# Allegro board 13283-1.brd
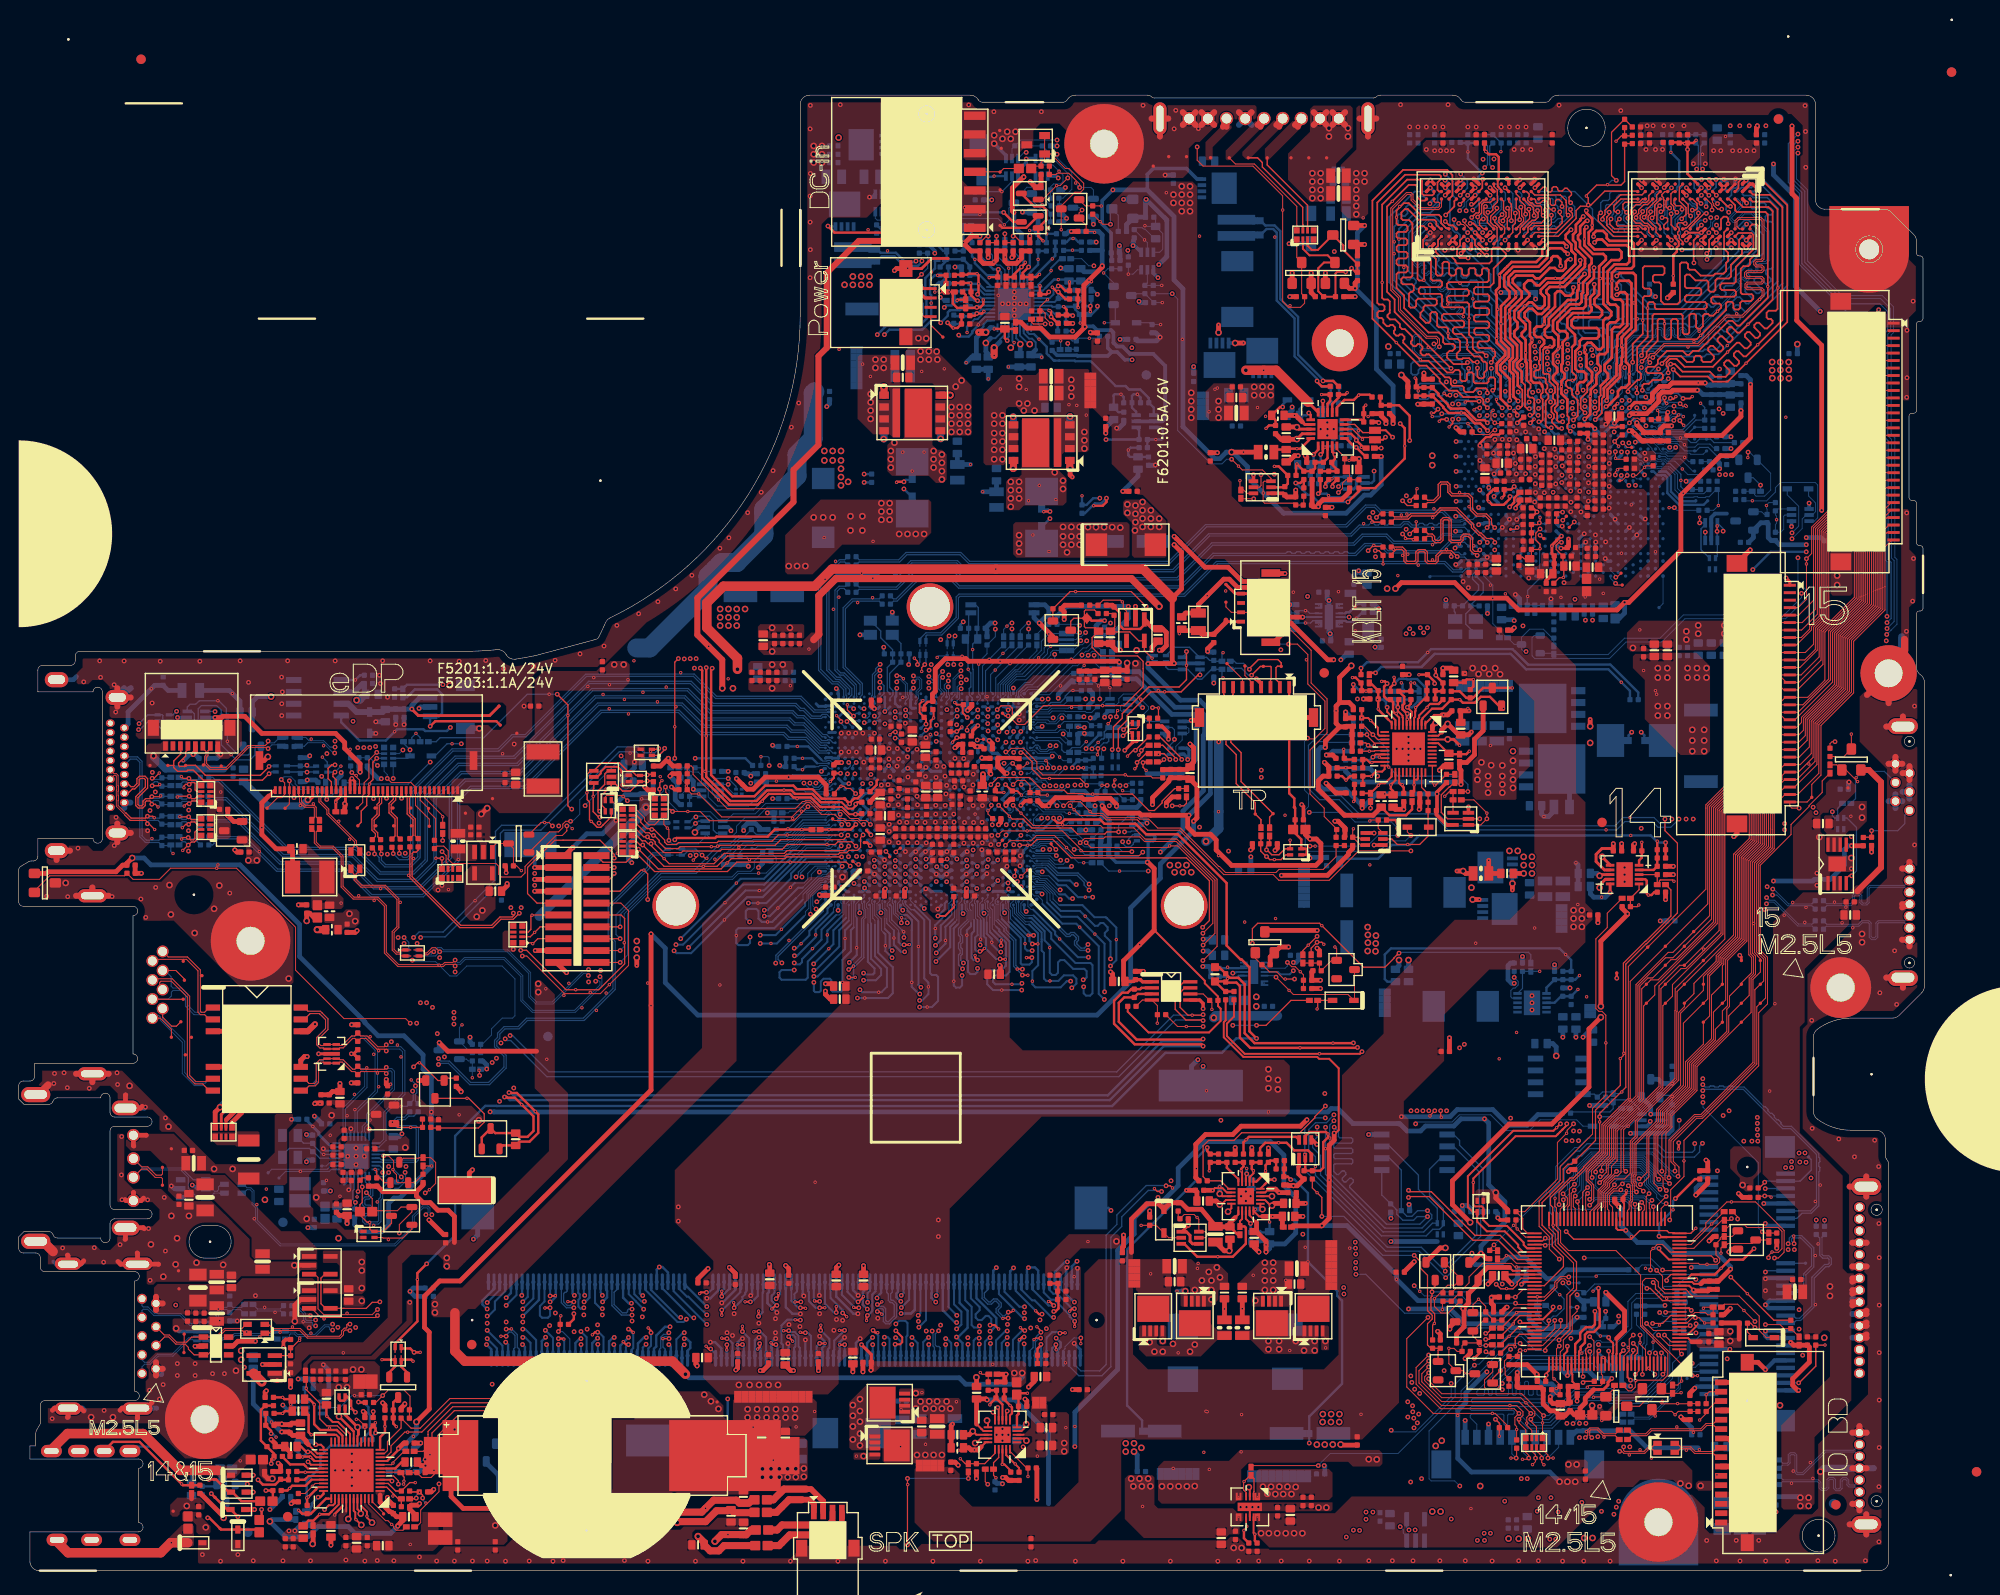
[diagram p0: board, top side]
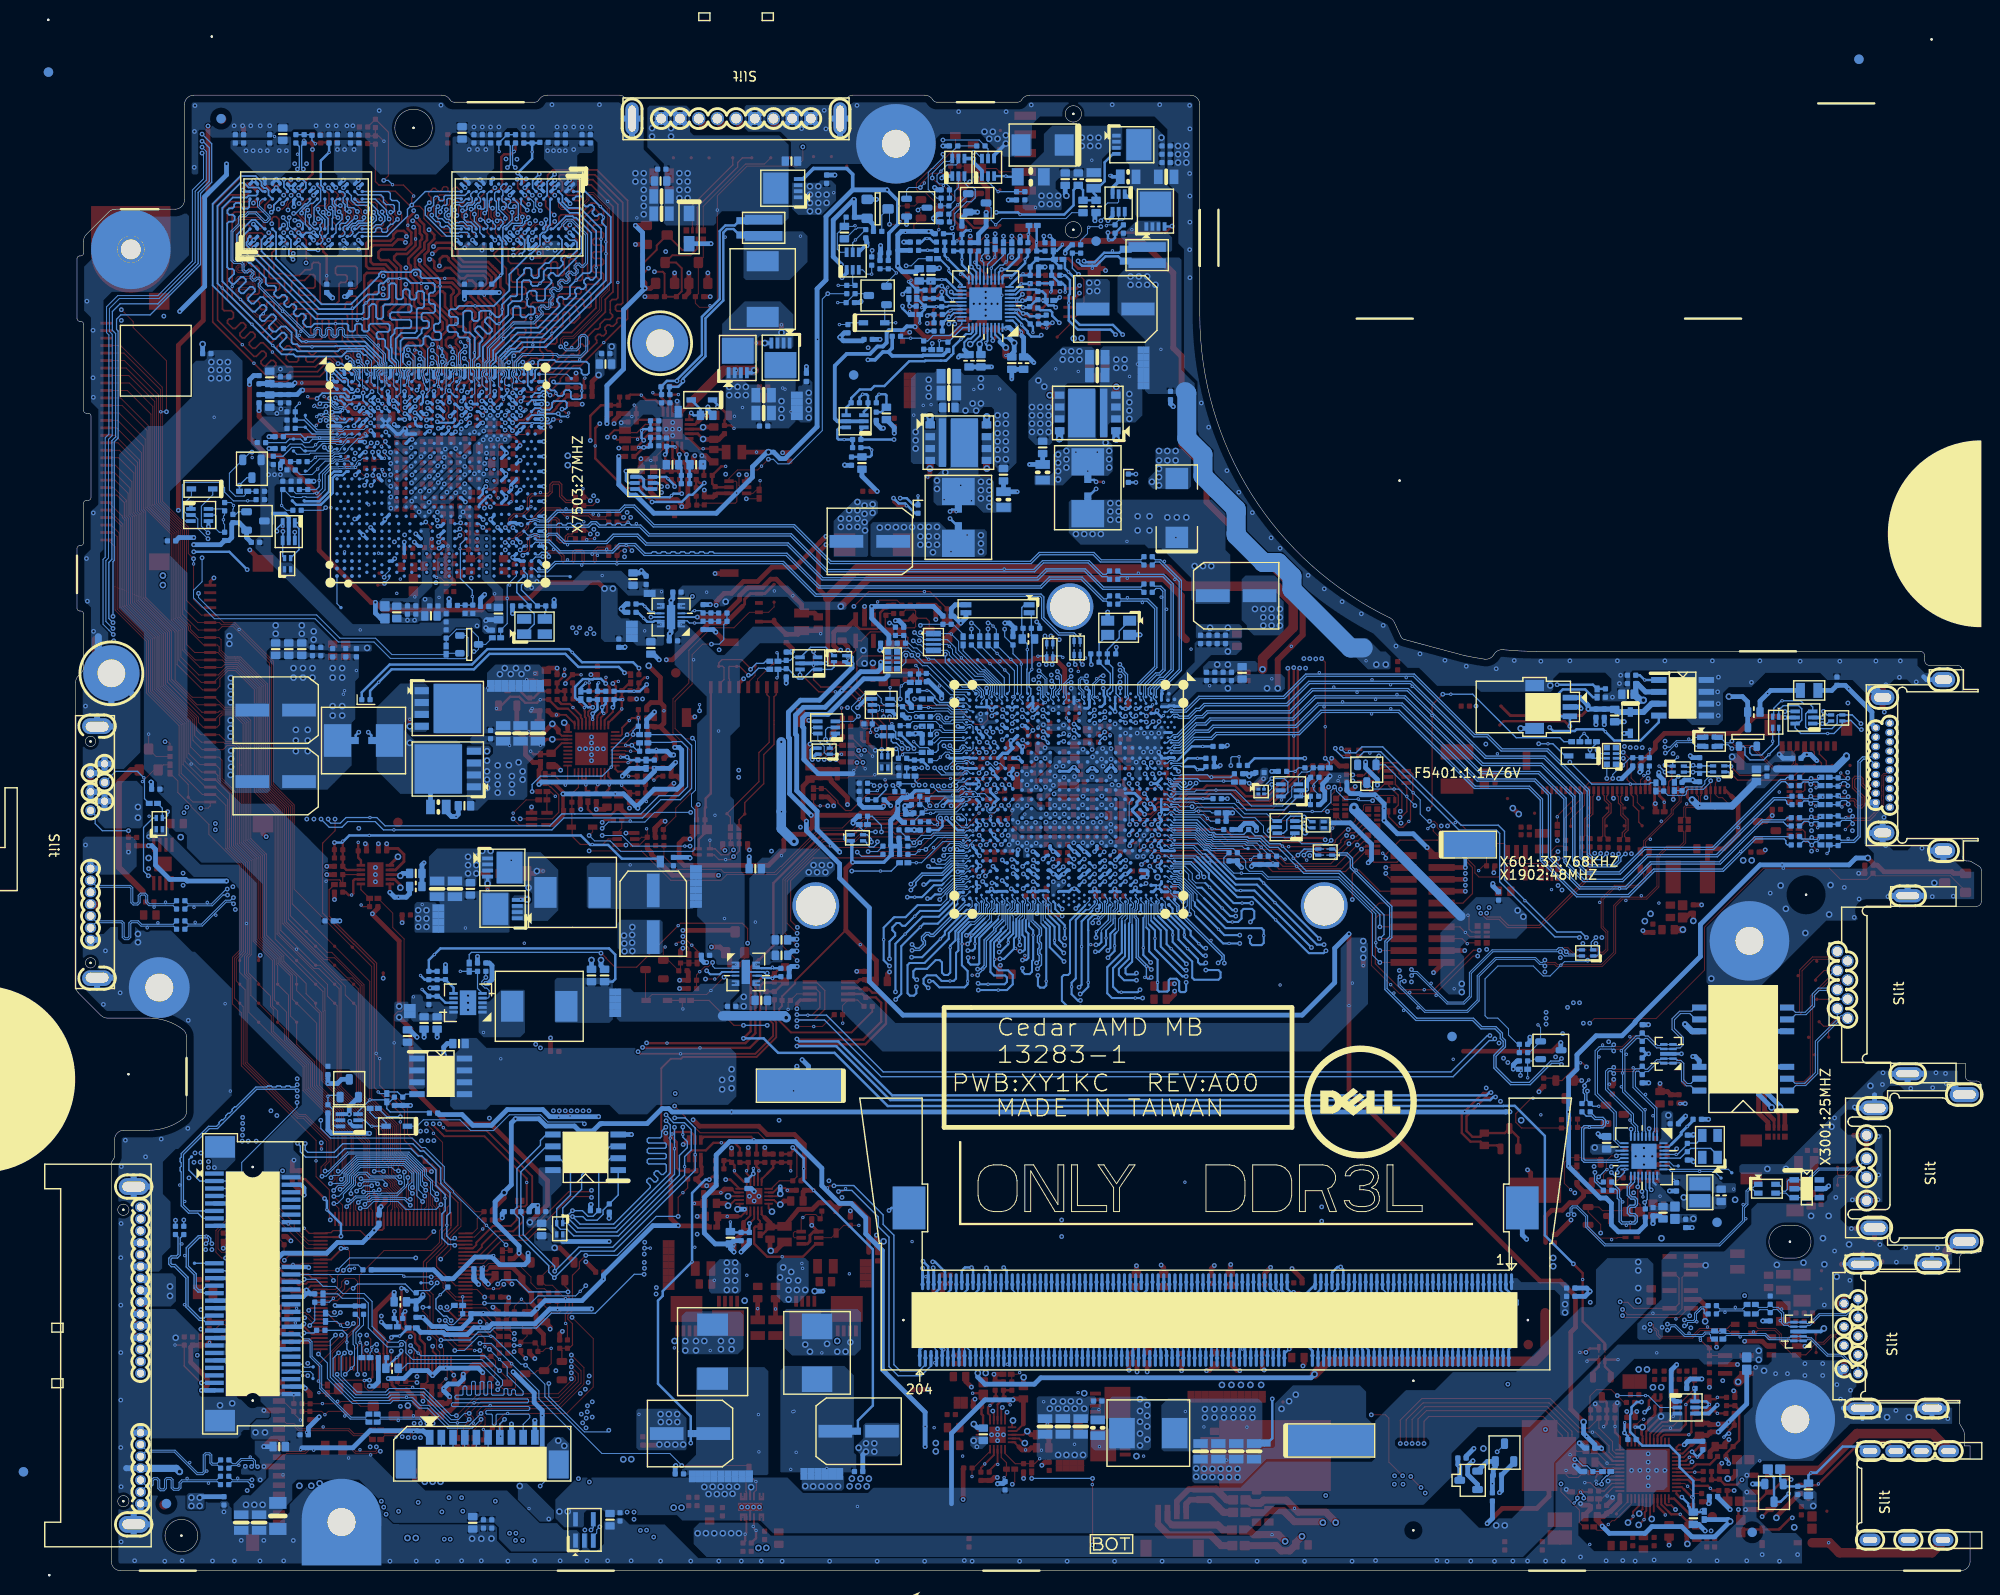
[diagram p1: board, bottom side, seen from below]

Outline 203.85 x 157.9 mm; copper layers: TOP, L2VCC, L3, L4, L5GND, BOTTOM. Coordinates in mm from the lower left corner of the outline.

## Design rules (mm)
constraint set DEFAULT: min track width 0.127, pair gap 0.102
net group APU_4_5: nets H_A20GATE PM_PWRBTN#_R
net group APU_4_8: nets PM_RSMRST# PM_RSMRST#_R
net group APU_SPI_CLK: nets APU_SPI_CLK SPI_CLK_R
net group APU_SPI_CS0#: nets APU_SPI_CS0# SPI_CS0#_R
net group APU_SPI_HOLD#: nets APU_SPI_HOLD# SPI_HOLD#
net group APU_SPI_SI_R: nets APU_SPI_SI_R SPI_SI_R
net group APU_SPI_SO_R: nets APU_SPI_SO_R SPI_SO_R
net group APU_SPI_WP#: nets APU_SPI_WP# SPI_WP#
net group CLK_MINI1#_R: nets CLK_MINI1#_R CLK_PCIE_WLAN_N1
net group CLK_MINI1_R: nets CLK_MINI1_R CLK_PCIE_WLAN_P1
net group CLK_PCIE_LAN_N0: nets CLK_PCIE_LAN_N0 CLK_PCIE_LAN_N0_R
net group CLK_PCIE_LAN_P0: nets CLK_PCIE_LAN_P0 CLK_PCIE_LAN_P0_R
net group CLK_PCIE_VGA: nets CLK_PCIE_VGA FCHGFX_CLKP_R
net group CLK_PCIE_VGA#: nets CLK_PCIE_VGA# FCHGFX_CLKN_R
net group CRT-MW: nets DAC_HSYNC DAC_ZVSS
net group DDC_CLK_HDMI: nets DDC_CLK_HDMI PCH_HDMI_CLK
net group DDC_DATA_HDMI: nets DDC_DATA_HDMI PCH_HDMI_DATA
net group DDR3_DQS: nets M_A_DQS_DN<4> M_A_DQS_DP<4>
net group DDR_RST-MW: nets DDR3_DRAMRST# M_A_EVENT#
net group EDP_AUX: nets EDP_AUX EDP_AUX_DP
net group EDP_AUX#: nets EDP_AUX# EDP_AUX_DN
net group EDP_TX0: nets EDP_TX0 EDP_TX0_DP
net group EDP_TX0#: nets EDP_TX0# EDP_TX0_DN
net group EDP_TX1: nets EDP_TX1 EDP_TX1_DP
net group EDP_TX1#: nets EDP_TX1# EDP_TX1_DN
net group FAN_TACH: nets FAN_TACH1 FAN_TACH1_C
net group GTXN0: nets GTXN0 PEG_TXN0
net group GTXN1: nets GTXN1 PEG_TXN1
net group GTXN2: nets GTXN2 PEG_TXN2
net group GTXN3: nets GTXN3 PEG_TXN3
net group GTXP0: nets GTXP0 PEG_TXP0
net group GTXP1: nets GTXP1 PEG_TXP1
net group GTXP2: nets GTXP2 PEG_TXP2
net group GTXP3: nets GTXP3 PEG_TXP3
net group LAN_TXN_C_PCH_RXN0: nets LAN_TXN_C_PCH_RXN0 PCIE_PRX_LANTX_N0
net group LAN_TXP_C_PCH_RXP0: nets LAN_TXP_C_PCH_RXP0 PCIE_PRX_LANTX_P0
net group PCIE_PTX_LANRX_N0: nets PCIE_PTX_LANRX_N0 PCIE_PTX_LANRX_N0_C
net group PCIE_PTX_LANRX_P0: nets PCIE_PTX_LANRX_P0 PCIE_PTX_LANRX_P0_C
net group PCIE_PTX_WLANRX_N1_C: nets PCIE_PTX_WLANRX_N1_C PCIE_TXN1_C
net group PCIE_PTX_WLANRX_P1_C: nets PCIE_PTX_WLANRX_P1_C PCIE_TXP1_C
net group PEG_C_RXN0: nets PEG_C_RXN0 PEG_RXN0
net group PEG_C_RXN1: nets PEG_C_RXN1 PEG_RXN1
net group PEG_C_RXN2: nets PEG_C_RXN2 PEG_RXN2
net group PEG_C_RXN3: nets PEG_C_RXN3 PEG_RXN3
net group PEG_C_RXP0: nets PEG_C_RXP0 PEG_RXP0
net group PEG_C_RXP1: nets PEG_C_RXP1 PEG_RXP1
net group PEG_C_RXP2: nets PEG_C_RXP2 PEG_RXP2
net group PEG_C_RXP3: nets PEG_C_RXP3 PEG_RXP3
net group SATA_PRX_HDDTX_N0: nets SATA_PRX_HDDTX_N0 SATA_RXN0_R
net group SATA_PRX_HDDTX_P0: nets SATA_PRX_HDDTX_P0 SATA_RXP0_R
net group SATA_PRX_ODDTX_N1: nets SATA_PRX_ODDTX_N1 SATA_RXN2_R
net group SATA_PRX_ODDTX_P1: nets SATA_PRX_ODDTX_P1 SATA_RXP2_R
net group SATA_PTX_HDDRX_N0: nets SATA_PTX_HDDRX_N0 SATA_TXN0_R
net group SATA_PTX_HDDRX_P0: nets SATA_PTX_HDDRX_P0 SATA_TXP0_R
net group SATA_PTX_ODDRX_N1: nets SATA_PTX_ODDRX_N1 SATA_TXN2_R
net group SATA_PTX_ODDRX_P1: nets SATA_PTX_ODDRX_P1 SATA_TXP2_R
net group USB3_PTX_CRX_N0: nets USB3_PTX_CRX_N0 USB3_PTX_CRX_N0_R
net group USB3_PTX_CRX_P0: nets USB3_PTX_CRX_P0 USB3_PTX_CRX_P0_R
net group USB4-DIFF: nets USB_PN4 USB_PP4
net group USB5-DIFF: nets USB_PN5 USB_PP5
net group USB6-DIFF: nets USB_PN6 USB_PP6
net group USB30_RX0-DIFF: nets USB3_PRX_CTX_N0 USB3_PRX_CTX_P0
net group USB_PN0: nets USB_PN0 USB_PP0_R
net group USB_PN0_R: nets USB_PN0_R USB_PP0
net group USB_PN8: nets USB_PN8 USB_PP8_C
net group USB_PN8_C: nets USB_PN8_C USB_PP8
net group APU_4_12: nets APU_PWROK APU_PWROK_HDT APU_SIC APU_SID H_PROCHOT# H_PROCHOT#_EC PQ4008_6 PQ4405_3 PROCHOT_EC
net group APU_TEST_4: nets APU_TEST0 APU_TEST1 APU_TEST2 APU_TEST6_DIRECRACKMON APU_TEST14_BP0 APU_TEST15_BP1 APU_TEST16_BP2 APU_TEST17_BP3 APU_TEST18_PLLTEST1 APU_TEST19_PLLTEST0 APU_TEST28_H_PLLCHRZ APU_TEST28_L_PLLCHRZ APU_TEST31_M_TEST APU_TEST36_FREE_2 APU_TEST37_FREE_2 BYPASSCLK_H BYPASSCLK_L
net group APU_ZVSS: nets DP_2K_ZVSS DP_150_ZVSS M_ZVDDIO P_RX_ZVDD_095 P_TX_ZVDD_095 SATA_ZVDD_095 SATA_ZVSS USB_RCOMP USB_SS_ZVDD_095 USB_SS_ZVSS
net group AUDIO_BEEP: nets AUD_HP1_JACK_L AUD_HP1_JACK_L1 AUD_HP1_JACK_R AUD_HP1_JACK_R1 AUD_PC_BEEP AUD_PC_BEEP_C AUD_PORTA_L_R_B AUD_PORTA_R_R_B AUD_SENSE AUD_SENSE_A AUD_VREF CBN CBP HDA_SPKR HDA_SPKR_R JACK_PLUG JACK_PLUG_DET KBC_BEEP KBC_BEEP_R LINE1-L_C LINE1-L_R LINE1_L LINE1_R LINE1_VREFO_L LINE1_VREFO_R MIC2_VREFO SLEEVE_CTRL
net group AUDIO_BEEP1: nets AUD_SPK_L+ AUD_SPK_L+_C AUD_SPK_L- AUD_SPK_L-_C AUD_SPK_R+ AUD_SPK_R+_C AUD_SPK_R- AUD_SPK_R-_C
net group AUDIO_BITCLK-MW: nets CODEC_BITCLK_R HDA_CODEC_BITCLK HDA_CODEC_BITCLK_R
net group AUDIO_DIGITAL-MW: nets CODEC_SDOUT_R HDA_CODEC_RST# HDA_CODEC_RST#_R HDA_CODEC_SDIN0 HDA_CODEC_SDOUT HDA_CODEC_SDOUT_R HDA_CODEC_SYNC HDA_CODEC_SYNC_R HDA_SDIN0
net group CARD_12MIL: nets RSET
net group CLK: nets CLK_PCI_KBC CLK_PCI_LPC CLKTESTA CLKTESTA_C CLKTESTB CLKTESTB_C
net group CLK-REQ: nets CLK_LAN_REQ0#_R CLK_PCIE_LAN_REQ0# CLK_PCIE_WLAN_REQ1# CLKREQG# VGA_PEG_CLKREQ#
net group CRT_B: nets DAC_BLUE
net group CRT_G: nets DAC_GREEN
net group CRT_R: nets DAC_RED
net group DDR3_A_DM: nets M_A_DM4 M_A_DQ<32> M_A_DQ<33> M_A_DQ<34> M_A_DQ<35> M_A_DQ<36> M_A_DQ<37> M_A_DQ<38> M_A_DQ<39>
net group DDR3_ADDR: nets M_A_A0 M_A_A1 M_A_A2 M_A_A3 M_A_A4 M_A_A5 M_A_A6 M_A_A7 M_A_A8 M_A_A9 M_A_A10 M_A_A11 M_A_A12 M_A_A13 M_A_A14 M_A_A15 M_A_BS0 M_A_BS1 M_A_BS2 M_A_CAS# M_A_RAS# M_A_WE# M_B_DIM0_CKE0 M_B_DIM0_CKE1 M_B_DIM0_CS#0 M_B_DIM0_CS#1 M_B_DIM0_ODT0 M_B_DIM0_ODT1
net group DDR3_CLK: nets M_B_DIM0_CLK_DDR0 M_B_DIM0_CLK_DDR1 M_B_DIM0_CLK_DDR#0 M_B_DIM0_CLK_DDR#1
net group DDR3_DATA0: nets M_A_DM0 M_A_DQ<0> M_A_DQ<1> M_A_DQ<2> M_A_DQ<3> M_A_DQ<4> M_A_DQ<5> M_A_DQ<6> M_A_DQ<7> M_A_DQS_DN<0> M_A_DQS_DP<0>
net group DDR3_DATA1: nets M_A_DM1 M_A_DQ<8> M_A_DQ<9> M_A_DQ<10> M_A_DQ<11> M_A_DQ<12> M_A_DQ<13> M_A_DQ<14> M_A_DQ<15> M_A_DQS_DN<1> M_A_DQS_DP<1>
net group DDR3_DATA2: nets M_A_DM2 M_A_DQ<16> M_A_DQ<17> M_A_DQ<18> M_A_DQ<19> M_A_DQ<20> M_A_DQ<21> M_A_DQ<22> M_A_DQ<23> M_A_DQS_DN<2> M_A_DQS_DP<2>
net group DDR3_DATA3: nets M_A_DM3 M_A_DQ<24> M_A_DQ<25> M_A_DQ<26> M_A_DQ<27> M_A_DQ<28> M_A_DQ<29> M_A_DQ<30> M_A_DQ<31> M_A_DQS_DN<3> M_A_DQS_DP<3>
net group DDR3_DATA5: nets M_A_DM5 M_A_DQ<40> M_A_DQ<41> M_A_DQ<42> M_A_DQ<43> M_A_DQ<44> M_A_DQ<45> M_A_DQ<46> M_A_DQ<47> M_A_DQS_DN<5> M_A_DQS_DP<5>
net group DDR3_DATA6: nets M_A_DM6 M_A_DQ<48> M_A_DQ<49> M_A_DQ<50> M_A_DQ<51> M_A_DQ<52> M_A_DQ<53> M_A_DQ<54> M_A_DQ<55> M_A_DQS_DN<6> M_A_DQS_DP<6>
net group DDR3_DATA7: nets M_A_DM7 M_A_DQ<56> M_A_DQ<57> M_A_DQ<58> M_A_DQ<59> M_A_DQ<60> M_A_DQ<61> M_A_DQ<62> M_A_DQ<63> M_A_DQS_DN<7> M_A_DQS_DP<7>
net group GND: nets CAM1_MIC_GND EC_AGND MIC_GND
net group HDMI_CLK: nets HDMI_CLK HDMI_CLK_R HDMI_CLK_R_C
net group HDMI_CLK#: nets HDMI_CLK# HDMI_CLK#_R HDMI_CLK#_R_C
net group HDMI_DATA0: nets HDMI_DATA0 HDMI_DATA0_R HDMI_DATA0_R_C
net group HDMI_DATA0#: nets HDMI_DATA0# HDMI_DATA0#_R HDMI_DATA0#_R_C
net group HDMI_DATA1: nets HDMI_DATA1 HDMI_DATA1_R HDMI_DATA1_R_C
net group HDMI_DATA1#: nets HDMI_DATA1# HDMI_DATA1#_R HDMI_DATA1#_R_C
net group HDMI_DATA2: nets HDMI_DATA2 HDMI_DATA2_R HDMI_DATA2_R_C
net group HDMI_DATA2#: nets HDMI_DATA2# HDMI_DATA2#_R HDMI_DATA2#_R_C
net group HDT_APU: nets APU_DBRDY APU_DBREQ# APU_TCK APU_TDI APU_TDO APU_TMS APU_TRST# DBRDY1 DBRDY2 DBRDY3
net group JTAG: nets JTAG_TCK_VGA JTAG_TDI_VGA JTAG_TDO JTAG_TMS_VGA JTAG_TRST#_VGA
net group JTAG_APU: nets APU_ALERT# APU_RST# APU_RST_L_BUF APU_SVC APU_SVD APU_SVT GPU_VGA_SVC GPU_VGA_SVD PWR_VCCCORE_SVC PWR_VCCCORE_SVD PWR_VCCCORE_SVT PWR_VGA_SVC PWR_VGA_SVD PWR_VGA_SVT
net group KB: nets KCOL0 KCOL1 KCOL2 KCOL3 KCOL4 KCOL5 KCOL6 KCOL7 KCOL8 KCOL9 KCOL10 KCOL11 KCOL12 KCOL13 KCOL14 KCOL15 KCOL16 KROW0 KROW1 KROW2 KROW3 KROW4 KROW5 KROW6 KROW7
net group LCD_BKLT-MW: nets BKLT_CTRL EC_BRIGHTNESS EDP_BKLT_CTRL L_BKLT_CTRL LCD_BRIGHTNESS
net group LED: nets AMBER_LED_BAT BAT_AMBER BAT_WHITE BATT_WHITE_LED# BATT_WHITE_LED_R# CAP_LED CAP_LED# CAP_LED_Q CAP_LED_R# CHG_AMBER_LED# CHG_AMBER_LED_R# SATA_LED# WHITE_LED_BAT
net group LPC: nets APU_LPC_AD0 APU_LPC_AD1 APU_LPC_AD2 APU_LPC_AD3 INT_SERIRQ LPC_AD0 LPC_AD1 LPC_AD2 LPC_AD3 LPC_FRAME# LPC_FRAME#_DEBUG LPC_FRAME#_R LPC_LAD0_R LPC_LAD1_R LPC_LAD2_R LPC_LAD3_R
net group OTHER_4MIL: nets 3.3V_RUN_VGA_1 51123_PGOOD_2 AC_IN# AC_IN_KBC# AC_PRESENT AD+_G_1 ALERT# AMP_MUTE# BAT_IN# BLINK BLON_OUT BLON_OUT_C BLUETOOTH_EN CARD_WLAN_OUT# CARD_WPAN_OUT# CEDAR_JANUS_ID COMBO-GPI CPVEE DBC_EN DBC_EN_R E51_TXD EAPD# EC_SCI# EC_SMI# EC_SWI# ECRST# ECSCI#_KBC ECSMI#_KBC ECSWI#_KBC EDP_HPD EDP_HPD_CONN EDP_VDD_EN GEVENT4# GEVENT7# GPIO5_AC_BATT GPIO8_ROMSO GPIO10_ROMSCK GPIO16_SSIN GPIO21_BB_EN GPIO71 GPIO_17_THERMAL_INT GPIO_19_CTF GPIO_22_ROMCS# GPUTHER_ALERT# H_RCIN# HDMI_HPD_B HDMI_HPD_E HDMI_PCH_DET HPD_HDMI_CON INT_TP# ISOLATE# JDREF KB_BL_CTRL KB_DET# KB_LED_BL_DET KB_LED_DET_C KBC_ON#_GATE KBC_ON#_GATE_L KBC_PWRBTN# L_BKLT_EN L_BKLT_EN_EC LCD_TST LCD_TST_C LCD_TST_EN LCDVDD_EN LDRQ0# LED0 LED1 LED2 LID_CLOSE# LPC_PD# LPC_RST# LPC_RST#_C M_ANALOGIN M_ANALOGOUT MEM_CALRN0 MEM_CALRP0 MODEL_ID_DET MUTE_CTRL N209551934 N209551965 PANEL_SIZE_ID PANEL_SIZE_ID_CONN PCB_VER_AD PD4403_A PD4403_K PE_GPIO0 PE_GPIO1 PM_CLKRUN#_EC PM_PWRBTN# PQ3802_1 PQ3808D PQ3808G PQ4203_5 PQ4405_2 PQ4405_5 PQ4405_6 PQ4408_C PQ4408_E PQ4502_2 PQ4502_5 PQ9302_G PR4601_1 PR9319_1 PSID_DISABLE#_R_C PSID_EC PSL_IN1# PSL_IN2# PSL_OUT# PWR_CHG_ACOK PWR_CHG_AD_OFF PWR_CHG_AD_OFF_R PWR_VCCCORE_ENABLE PWRCNTL_2 PWRCNTL_3 PWRCNTL_4 PX_EN Q402_1 Q603_2 RTC_1D5V_EN RTC_DET# SYS_RESET# TEMPINRETURN TP41 TP_RESET TP_RS TP_WAKE TX_PWRS_ENB USB_ATEST0 USB_ATEST1 VD1_EN# VGA_CORE_DISCHG VGA_DIS VRAM_SIZE1 VSS_MECH1 VSS_MECH2 VSS_MECH3 WIFI_RF_EN
net group OTHER_4MIL_2H: nets 0D95V_PWRGD 0D95V_S0_EN 0D95V_S5_PWRGD 1D8V_S5_PWRGD 1D35V_PGOOD ATI_RST# ATI_RST#_R DGPU_PRESENT# DGPU_PWR_EN# PM_SLP_S3# PS_ID PS_ID_R PS_ID_R2
net group OTHER_4MIL_3H: nets APU_RST#_C PLT_RST# PLT_RST#_EC
net group OTHER_5.5M: nets GPU_CLKA0_T GPU_CLKA1_T LPCCLK0 LPCCLK1 MEM_1V5 MEM_RST PCH_SUSCLK_KBC RTC_CLK
net group OTHER_10MIL: nets MVREFDA MVREFSA PCIE_CALRN PCIE_CALRP VDDIO_MEM_SENSE
net group PLATFORM: nets 0.95VGA_EN 0D95_S5_EN 1.8VGA_EN 1D5V_S0_EN 1D35V_ENABLE 1D35V_ENABLE_RC 1D35V_VGA_EN 1D35V_VGA_EN# 3V5V_S0_ON 3V_5V_EN 3V_5V_POK 8179A_EN/DEM_VGA AC_IN#_G ALL_SYS_PWRGD APU_DIGON APU_PWROK_C CLK_LAN_REQ#_EN DDR_VTT_PG_CTRL_R DGPU_PWROK DGPU_PWROK_R DRAM_RST DRAM_RST_R H_CPUPWRGD_REG HDMI_EN HDMI_HPD_DET IMVP_PWRGD KBC_PWRBTN#_C LAN_ENABLE_R_C MLPS_EN# PCIE_RST#_C PCIE_WAKE# PCIE_WAKE#_R PEG_CLKREQ# PLT_RST#_DEBUG PLT_RST#_LAN PM_LAN_ENABLE PM_LAN_ENABLE_R PM_SLP_S5# PS_0 PS_1 PS_2 PS_3 PWR_0D95V_EN PWR_0D95V_PWRGD PWR_1D8V_EN PWR_1D35V_EN PWR_APU_VDD_PGOOD PWR_VDDNB_PGOOD PWR_VGA_PGOOD PWR_VGA_PWROK PWRGOOD PWROK RSMRST#_KBC RTC_1D5V_PWR RTC_1D5V_S5 RTCRST_ON RUNPWROK_D S0_PWR_GOOD_R S5_ENABLE SATA_ODD_DA# SATA_ODD_DA#_C SATA_ODD_PRSNT# SATA_ODD_PWRGT SYS_PWRGD TESTEN TOUCH_PANEL_INTR# TOUCH_PANEL_INTR_KBC# TS_A USB_PWR_EN# V3D3_STB VCORE_EN VGA_PWROK
net group POWER_10M: nets 3V5V_CT1 3V5V_CT2 +3V_AVDD AD+_G_2 AD_IA AD_IA_HW AD_IA_HW2 BOOST_MODE# EC_VBKUP FAN1_DAC_1 LDO1_CAP LDO2_CAP LDO3_CAP MIC_CAP PQ4008_2 PWR_1D35V_VTTREF TP_VDD VTT_CT_3VC_1
net group POWER_10M_POWER: nets 3V5V_CT_105VC_2 AD_OFF_L AD_OFF_R APU_VDDNB_RUN_FB_H PH_APU_VDD PH_VDDNB PQ3809_D PWR_0D95V_CCM PWR_0D95V_FB PWR_0D95V_PWR PWR_0D95V_TRIP PWR_1D8V_FB PWR_1D8V_SVIN PWR_1D35V_MODE PWR_1D35V_REFIN PWR_1D35V_TRIP PWR_1D35V_VREF PWR_3D3V5V_ENTRIP PWR_3D3V_ENTRIP2 PWR_3D3V_ENTRIP2_L PWR_3D3V_FB2 PWR_3D3V_VOUT PWR_5V3D3V_ENLDO PWR_5V3D3V_ENM/SECFB PWR_5V3D3V_TON PWR_5V_ENTRIP1 PWR_5V_ENTRIP1_L PWR_5V_FB1 PWR_5V_VOUT PWR_APU_VDD_ISEN1N PWR_APU_VDD_ISEN1P PWR_CHG_ACDET PWR_CHG_BTST_R PWR_CHG_CMPIN PWR_CHG_CMPIN_R PWR_CHG_CMPIN_RR PWR_CHG_CMPOUT PWR_CHG_IFAULT PWR_CHG_ILIM PWR_CHG_IOUT PWR_CHG_REGN PWR_CHG_VCC PWR_COMP PWR_COMP_1 PWR_COMPA PWR_COMPA_1 PWR_FB PWR_FB_1 PWR_FBA PWR_FBA_1 PWR_IBIAS PWR_IMON PWR_IMON_1 PWR_IMON_2 PWR_IMON_3 PWR_IMON_4 PWR_IMONA PWR_IMONA_1 PWR_IMONA_2 PWR_IMONA_3 PWR_IMONA_4 PWR_ISENA PWR_OCP_L PWR_OFS PWR_OFSA PWR_PVCC PWR_RGND PWR_SET1 PWR_SET1_1 PWR_SET1_2 PWR_SET2 PWR_SET2_1 PWR_SET2_2 PWR_TONSET PWR_TONSET_1 PWR_TONSET_D PWR_TONSETA PWR_TONSETA_1 PWR_TONSETA_D PWR_VCC PWR_VDDIO PWR_VDDNB_ISENA1N PWR_VDDNB_ISENA1P PWR_VDDQ_SENSE_APU PWR_VGA_COMP PWR_VGA_COMP_1 PWR_VGA_CORE_ISEN1N PWR_VGA_CORE_ISEN1P PWR_VGA_FB PWR_VGA_FB_1 PWR_VGA_IBIAS PWR_VGA_IMON PWR_VGA_IMON1 PWR_VGA_IMON2 PWR_VGA_IMON4 PWR_VGA_IMON5 PWR_VGA_OCP_L PWR_VGA_OFS PWR_VGA_PH1 PWR_VGA_PVCC PWR_VGA_RGND PWR_VGA_SET1 PWR_VGA_SET1_1 PWR_VGA_SET1_2 PWR_VGA_SET2 PWR_VGA_SET2_1 PWR_VGA_SET2_2 PWR_VGA_TONSET PWR_VGA_TONSET_1 PWR_VGA_TONSET_D PWR_VGA_VCC PWR_VGA_VDDIO PWR_VGA_VO1 PWR_VGA_VREF PWR_VGA_VSEN PWR_VREF PWR_VSEN PWR_VSENA VDD_095_FB_H VDD_095_FB_L VO_APU_VDD VO_VDDNB VTT_CT_0.95V VTT_CT_1.8V
net group POWER_20M: nets 3D3V_AUX_KBC_VCC 3D3V_AUX_S5 5V_HDMI_S0_R +5V_AVDD +5V_KB_BL +RTC_VCC DC_IN_D KB_BL_CTRL# MCT0 MCT1 MCT2 MCT3 PR4605_2 PWR_1D35V_VBST PWR_CHG_BTST RTC_AUX_S5 RTC_PWR TPAN_VDD VBAT
net group POWER_20M_POWER: nets 3D3V_PWR_2 5V_HDMI_S0 5V_PWR_2 +5V_MINI_DEBUG DPEF_CALR MPV18 PWR_0D95V_BOOT PWR_0D95V_BOOT_R PWR_1D05V_SNUB PWR_3D3V_BOOT2 PWR_3D3V_BOOT2_1 PWR_3D3V_SNUB PWR_5V_BOOT1 PWR_5V_BOOT1_1 PWR_5V_SNUB PWR_APU_VDD_BOOT PWR_APU_VDD_BOOT_1 PWR_APU_VDD_SNUB PWR_VDDNB_BOOTA PWR_VDDNB_BOOTA_1 PWR_VDDNB_SNUB PWR_VGA_CORE_BOOT1 PWR_VGA_CORE_BOOT1_1 PWR_VGA_SNUB SPV10 SPV18 TSVDD
net group POWER_30M_POWER: nets PWR_APU_VDD_LGATE PWR_APU_VDD_UGATE PWR_VDDNB_LGATEA PWR_VDDNB_UGATEA
net group POWER_40M: nets 1D5V_S0 DIS_1D35V_VGA_S0 FAN_VCC1 LOM_TCT
net group REF10M: nets KBC_VCORF
net group SPI-MWS: nets EC_SPI_CLK_C EC_SPI_CS#_C EC_SPI_DI_C EC_SPI_DO_C SPI_CS2# SPI_SW
net group T8: nets VD_IN1 VD_IN1_C VD_OUT1#
net group THERM_10M: nets FON#
net group THERM_SHUTDOWN: nets PURE_HW_SHUTDOWN# T_CRIT# THERM_SYS_SHDN#
net group USB_CAMERA: nets USB_CAMERA USB_PP7 USB_PP7_CAM
net group USB_CAMERA#: nets USB_CAMERA# USB_PN7 USB_PN7_CAM#
net group USB_OC: nets USB_OC#0 USB_OC#1 USB_OC#3
net group VRAM_CTRLA-MWS: nets CASA0# CASA1# CKEA0 CKEA1 CSA0#_0 CSA1#_0 ODTA0 ODTA1 RASA0# RASA1# WEA0# WEA1#
net group VRAM_DATA-MWS: nets MDA0 MDA1 MDA2 MDA3 MDA4 MDA5 MDA6 MDA7 MDA8 MDA9 MDA10 MDA11 MDA12 MDA13 MDA14 MDA15 MDA16 MDA17 MDA18 MDA19 MDA20 MDA21 MDA22 MDA23 MDA24 MDA25 MDA26 MDA27 MDA28 MDA29 MDA30 MDA31 MDA32 MDA33 MDA34 MDA35 MDA36 MDA37 MDA38 MDA39 MDA40 MDA41 MDA42 MDA43 MDA44 MDA45 MDA46 MDA47 MDA48 MDA49 MDA50 MDA51 MDA52 MDA53 MDA54 MDA55 MDA56 MDA57 MDA58 MDA59 MDA60 MDA61 MDA62 MDA63
net group VRAM_DQM_A-MWS: nets DQMA0 DQMA1 DQMA2 DQMA3 DQMA4 DQMA5 DQMA6 DQMA7
net group VRAM_MAA-MWS: nets A_BA0 A_BA1 A_BA2 MAA0 MAA1 MAA2 MAA3 MAA4 MAA5 MAA6 MAA7 MAA8 MAA9 MAA10 MAA11 MAA12 MAA13 MAA14 MAA15
net group VRAM_ZQ: nets VRAM1_2_VREF VRAM3_4_VREF VRAM_ZQ1 VRAM_ZQ2 VRAM_ZQ3 VRAM_ZQ4
net group WLAN-MW: nets BT_ACT DEBUG E51_RX E51_TX WLAN_ACT
net group XTAL-MWS: nets 32K_X1 32K_X2 48M_X1 48M_X2 LANXIN LANXOUT XO_IN XTALIN XTALOUT

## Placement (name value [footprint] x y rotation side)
AFTP2501  AFTE14P-GP  [AFTE14P-75]  74.7 18.05 0 top
AFTP2502  AFTE14P-GP  [AFTE14P-75]  47.54 6.66 0 top
AFTP2801  AFTE14P-GP  [AFTE14P-75]  51.38 92.52 0 top
AFTP2802  AFTE14P-GP  [AFTE14P-75]  51.51 90.49 0 top
AFTP2803  AFTE14P-GP  [AFTE14P-75]  53.28 89.62 180 top
AFTP2901  AFTE14P-GP  [AFTE14P-75]  81.63 2.99 0 top
AFTP2902  AFTE14P-GP  [AFTE14P-75]  81.66 4.89 0 top
AFTP2903  AFTE14P-GP  [AFTE14P-75]  81.86 8.73 0 top
AFTP2904  AFTE14P-GP  [AFTE14P-75]  81.63 6.82 0 top
AFTP2906  AFTE14P-GP  [AFTE14P-75]  21.54 4.51 0 top
AFTP2907  AFTE14P-GP  [AFTE14P-75]  20.92 9.76 0 top
AFTP2908  AFTE14P-GP  [AFTE14P-75]  16.52 6.37 0 top
AFTP2909  AFTE14P-GP  [AFTE14P-75]  21 7.84 0 top
AFTP3101  AFTE14P-GP  [AFTE14P-75]  17.6 61.16 90 top
AFTP3102  AFTE14P-GP  [AFTE14P-75]  17.35 58.74 90 top
AFTP3103  AFTE14P-GP  [AFTE14P-75]  17.82 55.21 90 top
AFTP3104  AFTE14P-GP  [AFTE14P-75]  18.48 57.08 90 top
AFTP3105  AFTE14P-GP  [AFTE14P-75]  17.6 65.22 90 top
AFTP3106  AFTE14P-GP  [AFTE14P-75]  17.73 63.19 90 top
AFTP3107  AFTE14P-GP  [AFTE14P-75]  16.33 57.09 90 top
AFTP3108  AFTE14P-GP  [AFTE14P-75]  19.6 63.68 90 top
AFTP3801  AFTE14P-GP  [AFTE14P-75]  104.98 147.77 0 top
AFTP3802  AFTE14P-GP  [AFTE14P-75]  104.98 149.67 90 top
AFTP3803  AFTE14P-GP  [AFTE14P-75]  104.94 154.12 0 top
AFTP3805  AFTE14P-GP  [AFTE14P-75]  104.98 143.96 0 top
AFTP3806  AFTE14P-GP  [AFTE14P-75]  105.1 152.21 0 top
AFTP3901  AFTE14P-GP  [AFTE14P-75]  127.48 151.21 0 top
AFTP3902  AFTE14P-GP  [AFTE14P-75]  129.49 151.2 0 top
AFTP3903  AFTE14P-GP  [AFTE14P-75]  131.52 151.2 0 top
AFTP3904  AFTE14P-GP  [AFTE14P-75]  133.55 151.2 0 top
AFTP3905  AFTE14P-GP  [AFTE14P-75]  136.09 151.2 0 top
AFTP3906  AFTE14P-GP  [AFTE14P-75]  123.01 151.33 0 top
AFTP3907  AFTE14P-GP  [AFTE14P-75]  139.9 151.2 0 top
AFTP3908  AFTE14P-GP  [AFTE14P-75]  138 151.2 0 top
AFTP3909  AFTE14P-GP  [AFTE14P-75]  121.36 150.31 0 top
AFTP3910  AFTE14P-GP  [AFTE14P-75]  124.91 151.33 0 top
AFTP5201  AFTE14P-GP  [AFTE14P-75]  43.84 81.57 0 top
AFTP5202  AFTE14P-GP  [AFTE14P-75]  47.79 81.06 0 top
AFTP5203  AFTE14P-GP  [AFTE14P-75]  36.28 79.71 0 top
AFTP5204  AFTE14P-GP  [AFTE14P-75]  50.68 82.63 0 top
AFTP5205  AFTE14P-GP  [AFTE14P-75]  36.22 81.62 0 top
AFTP5206  AFTE14P-GP  [AFTE14P-75]  41.94 81.62 0 top
AFTP5207  AFTE14P-GP  [AFTE14P-75]  43.91 79.67 0 top
AFTP5208  AFTE14P-GP  [AFTE14P-75]  42.01 79.71 0 top
AFTP5209  AFTE14P-GP  [AFTE14P-75]  28.5 81.59 90 top
AFTP5210  AFTE14P-GP  [AFTE14P-75]  40.1 79.71 0 top
AFTP5211  AFTE14P-GP  [AFTE14P-75]  38.2 79.71 0 top
AFTP5212  AFTE14P-GP  [AFTE14P-75]  38.13 81.62 0 top
AFTP5213  AFTE14P-GP  [AFTE14P-75]  40.03 81.62 0 top
AFTP5214  AFTE14P-GP  [AFTE14P-75]  26.57 81.6 0 top
AFTP5222  AFTE14P-GP  [AFTE14P-75]  15.95 86.17 0 top
AFTP5225  AFTE14P-GP  [AFTE14P-75]  19.76 86.22 0 top
AFTP5226  AFTE14P-GP  [AFTE14P-75]  21.66 86.1 0 top
AFTP5227  AFTE14P-GP  [AFTE14P-75]  14.04 86.17 0 top
AFTP5228  AFTE14P-GP  [AFTE14P-75]  17.85 86.17 0 top
AFTP6201  AFTE14P-GP  [AFTE14P-75]  184.27 65.3 0 top
AFTP6202  AFTE14P-GP  [AFTE14P-75]  191.8 82.76 0 top
AFTP6203  AFTE14P-GP  [AFTE14P-75]  176.14 64.79 0 top
AFTP6204  AFTE14P-GP  [AFTE14P-75]  15.38 43.16 0 top
AFTP6205  AFTE14P-GP  [AFTE14P-75]  16.33 45.15 0 top
AFTP6206  AFTE14P-GP  [AFTE14P-75]  180.2 65.3 0 top
AFTP6207  AFTE14P-GP  [AFTE14P-75]  176.14 62.76 0 top
AFTP6208  AFTE14P-GP  [AFTE14P-75]  178.17 62.76 0 top
AFTP6209  AFTE14P-GP  [AFTE14P-75]  15.38 41.25 0 top
AFTP6210  AFTE14P-GP  [AFTE14P-75]  17.14 30.17 0 top
AFTP6211  AFTE14P-GP  [AFTE14P-75]  17.7 25.31 0 top
AFTP6212  AFTE14P-GP  [AFTE14P-75]  17.68 23.34 0 top
AFTP6213  AFTE14P-GP  [AFTE14P-75]  180.2 60.73 0 top
AFTP6214  AFTE14P-GP  [AFTE14P-75]  184.27 60.73 0 top
AFTP6215  AFTE14P-GP  [AFTE14P-75]  182.24 62.76 0 top
AFTP6216  AFTE14P-GP  [AFTE14P-75]  178.17 66.82 0 top
AFTP6217  AFTE14P-GP  [AFTE14P-75]  17.09 32.1 0 top
AFTP6218  AFTE14P-GP  [AFTE14P-75]  184.27 58.69 0 top
AFTP6219  AFTE14P-GP  [AFTE14P-75]  179.17 68.39 0 top
AFTP6220  AFTE14P-GP  [AFTE14P-75]  176.14 66.82 0 top
AFTP6221  AFTE14P-GP  [AFTE14P-75]  186.3 60.73 0 top
AFTP6222  AFTE14P-GP  [AFTE14P-75]  186.3 62.76 0 top
AFTP6223  AFTE14P-GP  [AFTE14P-75]  180.2 62.76 0 top
AFTP6224  AFTE14P-GP  [AFTE14P-75]  180.2 58.69 0 top
AFTP6225  AFTE14P-GP  [AFTE14P-75]  174.11 60.73 0 top
AFTP6226  AFTE14P-GP  [AFTE14P-75]  176.14 60.73 0 top
AFTP6227  AFTE14P-GP  [AFTE14P-75]  184.27 62.76 0 top
AFTP6228  AFTE14P-GP  [AFTE14P-75]  182.24 60.73 0 top
AFTP6229  AFTE14P-GP  [AFTE14P-75]  174.11 62.76 0 top
AFTP6230  AFTE14P-GP  [AFTE14P-75]  186.3 65.3 0 top
AFTP6231  AFTE14P-GP  [AFTE14P-75]  178.17 60.73 0 top
AFTP6232  AFTE14P-GP  [AFTE14P-75]  174.25 66.72 0 top
AFTP6233  AFTE14P-GP  [AFTE14P-75]  178.17 64.79 0 top
AFTP6234  AFTE14P-GP  [AFTE14P-75]  182.24 58.69 0 top
AFTP6235  AFTE14P-GP  [AFTE14P-75]  170.94 63.96 0 top
AFTP6236  AFTE14P-GP  [AFTE14P-75]  134.18 81.01 0 top
AFTP6237  AFTE14P-GP  [AFTE14P-75]  133.13 96.77 0 top
AFTP6238  AFTE14P-GP  [AFTE14P-75]  132.27 80.98 0 top
AFTP6239  AFTE14P-GP  [AFTE14P-75]  136.45 81.7 0 top
AFTP6240  AFTE14P-GP  [AFTE14P-75]  135.05 96.77 0 top
AFTP6241  AFTE14P-GP  [AFTE14P-75]  131.16 96.82 0 top
AFTP6242  AFTE14P-GP  [AFTE14P-75]  129.25 97.07 0 top
AFTP6245  AFTE14P-GP  [AFTE14P-75]  195.67 83.78 0 top
AFTP6246  AFTE14P-GP  [AFTE14P-75]  129.13 103.64 0 top
AFTP6247  AFTE14P-GP  [AFTE14P-75]  129.13 105.55 0 top
AFTP6248  AFTE14P-GP  [AFTE14P-75]  129.13 101.74 0 top
AFTP6801  AFTE14P-GP  [AFTE14P-75]  98.85 132.02 0 top
AFTP6802  AFTE14P-GP  [AFTE14P-75]  99.39 140.43 0 top
BAT1  ALP-CON9-6-GP-U  [C144LC-109A7-L-U]  133.2 155.4 0 bottom
C1  HOLE197R166-1-GP  [HOLE197R166]  97.48 103.16 0 top
C2  HOLE197R166-1-GP  [HOLE197R166]  124.67 71.17 0 top
C3  HOLE197R166-1-GP  [HOLE197R166]  70.29 71.17 0 top
C303  SCD1U16V2KX-3GP  [C402H22]  193.16 36.42 180 bottom
C304  SCD1U16V2KX-3GP  [C402H22]  192.28 36.42 180 bottom
C305  SCD1U16V2KX-3GP  [C402H22]  41.83 49.55 180 bottom
C306  SCD1U16V2KX-3GP  [C402H22]  42.72 49.55 180 bottom
C401  SC150P50V2KX-GP  [C402H22]  71.3 84.9 270 bottom
C402  SC150P50V2KX-GP  [C402H22]  74.75 85.54 270 bottom
C441  SCD1U16V2KX-3GP  [C402H22]  89.13 107.62 270 bottom
C443  SCD1U16V2KX-3GP  [C402H22]  77.16 85.41 90 bottom
C445  SCD1U16V2KX-3GP  [C402H22]  92.81 104.32 270 bottom
C447  SCD1U16V2KX-3GP  [C402H22]  89.13 104.7 270 bottom
C448  SCD1U16V2KX-3GP  [C402H22]  89.13 108.51 270 bottom
C452  SCD1U16V2KX-3GP  [C402H22]  92.81 106.1 270 bottom
C457  SCD1U16V2KX-3GP  [C402H22]  89.13 105.59 270 bottom
C477  SCD1U16V2KX-3GP  [C402H22]  92.81 103.43 270 bottom
C478  SCD1U16V2KX-3GP  [C402H22]  92.81 106.99 270 bottom
C501  SCD1U10V2KX-5GP  [C402H22]  87.2 72.71 0 top
C502  SC1KP50V2KX-1GP  [C402H22]  86.31 72.71 0 top
C601  SC150P50V2KX-GP  [C402H22]  115.39 86.94 270 bottom
C603  SC8P50V2DN-1GP  [C402H22]  101.17 100.85 90 bottom
C604  SC10P50V2JN-4GP  [C402H22]  102.94 100.85 270 bottom
C605  SCD1U25V2KX-L-GP  [C402H22]  119.58 80.74 270 bottom
C701  SC1U10V3KX-3GP  [C603H36]  115.52 99.89 0 top
C702  SC1U10V3KX-3GP  [C603H36]  116.79 99.89 0 top
C703  SC10U6D3V3MX-GP  [C603H38]  96.97 87.7 0 top
C704  SC1U6D3V2KX-GP  [C402H22]  94.43 89.1 180 top
C705  SC1U10V3KX-3GP  [C603H36]  121.87 100.14 0 top
C762  SC10U6D3V3MX-GP  [C603H38]  95.58 89.35 180 top
C1001  SC1U10V2KX-1GP  [C402H22]  104.34 86.94 90 top
C1002  SC1U10V2KX-1GP  [C402H22]  117.29 99.26 270 bottom
C1003  SC180P50V2JN-1GP  [C402H22]  83.51 99.66 0 bottom
C1004  SC1U6D3V2KX-GP  [C402H22]  80.85 99.66 180 top
C1005  SC1U6D3V2KX-GP  [C402H22]  80.85 99.66 0 bottom
C1006  SC1U6D3V2KX-GP  [C402H22]  81.73 99.66 0 bottom
C1007  SC1U6D3V2KX-GP  [C402H22]  83.51 99.66 180 top
C1008  SC1U6D3V2KX-GP  [C402H22]  82.62 99.66 180 top
C1009  SC1U6D3V2KX-GP  [C402H22]  81.73 99.66 180 top
C1010  SC4D7U6D3V3KX-GP  [C603H36]  79.64 99.58 180 top
C1011  SC180P50V2JN-1GP  [C402H22]  82.62 99.66 0 bottom
C1012  SC1U6D3V2KX-GP  [C402H22]  101.42 87.57 270 top
C1013  SC1U6D3V2KX-GP  [C402H22]  100.58 85.79 0 top
C1014  SC1U6D3V2KX-GP  [C402H22]  99.77 85.79 0 top
C1015  SC4D7U6D3V3KX-GP  [C603H36]  117.45 95.7 180 top
C1016  SC4D7U6D3V3KX-GP  [C603H36]  116.18 95.7 180 top
C1022  SC180P50V2JN-1GP  [C402H22]  104.34 86.05 90 top
C1023  SC1U10V2KX-1GP  [C402H22]  102.66 86.05 270 top
C1024  SC1U10V2KX-1GP  [C402H22]  115.52 80.97 90 bottom
C1025  SC180P50V2JN-1GP  [C402H22]  82.88 95.7 0 bottom
C1026  SC1U6D3V2KX-GP  [C402H22]  81.99 95.7 0 bottom
C1027  SC1U6D3V2KX-GP  [C402H22]  80.21 95.7 180 top
C1028  SC1U6D3V2KX-GP  [C402H22]  81.1 95.7 180 top
C1029  SC1U6D3V2KX-GP  [C402H22]  81.1 95.7 0 bottom
C1030  SC1U6D3V2KX-GP  [C402H22]  80.21 95.7 0 bottom
C1031  SC1U6D3V2KX-GP  [C402H22]  78.43 95.7 180 top
C1032  SC1U6D3V2KX-GP  [C402H22]  79.32 95.7 180 top
C1033  SC4D7U6D3V3KX-GP  [C603H36]  79.07 96.08 0 bottom
C1034  SC180P50V2JN-1GP  [C402H22]  103.71 87.95 90 top
C1035  SC1U6D3V2KX-GP  [C402H22]  101.42 88.43 270 top
C1036  SC1U6D3V2KX-GP  [C402H22]  124.17 85.3 180 top
C1037  SC1U6D3V2KX-GP  [C402H22]  123.23 85.3 180 top
C1038  SC4D7U6D3V3KX-GP  [C603H36]  125.3 85.36 180 top
C1039  SC180P50V2JN-1GP  [C402H22]  100.91 78.96 0 top
C1040  SC1U6D3V2KX-GP  [C402H22]  101.8 78.96 0 top
C1041  SC1U6D3V2KX-GP  [C402H22]  102.61 78.96 0 top
C1042  SC1U6D3V2KX-GP  [C402H22]  103.43 78.96 0 top
C1043  SC1U6D3V2KX-GP  [C402H22]  100.28 82.01 270 top
C1044  SC1U6D3V2KX-GP  [C402H22]  100.28 82.9 270 top
C1045  SC1U6D3V2KX-GP  [C402H22]  101.78 83.01 180 top
C1046  SC4D7U6D3V3KX-GP  [C603H36]  131.14 75.13 270 bottom
C1047  SC22U6D3V3MX-1-GP  [C603H40]  128.34 67.51 90 bottom
C1049  SC180P50V2JN-1GP  [C402H22]  105.99 76.9 90 top
C1050  SC180P50V2JN-1GP  [C402H22]  90.37 74.88 270 top
C1051  SC180P50V2JN-1GP  [C402H22]  98.63 77.28 0 top
C1053  SC4D7U6D3V3KX-GP  [C603H36]  104.34 63.83 90 top
C1054  SC4D7U6D3V3KX-GP  [C603H36]  87.83 61.16 270 top
C1055  SC4D7U6D3V3KX-GP  [C603H36]  87.83 62.56 270 top
C1056  SCD1U10V2KX-4GP  [C402H20]  100.02 77.28 0 top
C1057  SCD1U10V2KX-4GP  [C402H20]  104.21 76.9 270 top
C1058  SCD1U10V2KX-4GP  [C402H20]  105.99 76.09 270 top
C1059  SCD1U10V2KX-4GP  [C402H20]  101.8 72.2 90 top
C1060  SCD1U10V2KX-4GP  [C402H20]  97.74 77.28 180 top
C1061  SCD1U10V2KX-4GP  [C402H20]  94.31 72.2 270 top
C1062  SCD1U10V2KX-4GP  [C402H20]  92.15 72.2 270 top
C1063  SCD1U10V2KX-4GP  [C402H20]  91.64 76.9 270 top
C1064  SC22U6D3V3MX-1-GP  [C603H40]  98.3 83.38 0 top
C1065  SC22U6D3V3MX-1-GP  [C603H40]  97.03 83.38 0 top
C1066  SC22U6D3V3MX-1-GP  [C603H40]  91.64 87.83 270 top
C1067  SC180P50V2JN-1GP  [C402H22]  91.64 88.99 270 top
C1068  SC1U6D3V2KX-GP  [C402H22]  93.75 90.37 90 top
C1069  SC1U6D3V2KX-GP  [C402H22]  96.34 85.67 180 top
C1070  SC1U6D3V2KX-GP  [C402H22]  94.18 84.14 0 top
C1071  SC1U6D3V2KX-GP  [C402H22]  98.12 87.19 180 top
C1072  SC1U6D3V2KX-GP  [C402H22]  95.96 83.97 0 top
C1073  SC1U6D3V2KX-GP  [C402H22]  100.53 84.52 90 top
C1074  SC1U6D3V2KX-GP  [C402H22]  91.64 86.76 270 top
C1075  SC1U6D3V2KX-GP  [C402H22]  91.64 85.92 270 top
C1076  SC1U6D3V2KX-GP  [C402H22]  91.64 93.16 270 top
C1077  SC22U6D3V3MX-1-GP  [C603H40]  92.15 82.62 180 top
C1078  SC22U6D3V3MX-1-GP  [C603H40]  92.67 80.79 90 top
C1079  SC22U6D3V3MX-1-GP  [C603H40]  92.15 78.83 0 top
C1080  SC180P50V2JN-1GP  [C402H22]  93.8 78.99 0 top
C1081  SC1U6D3V2KX-GP  [C402H22]  94.69 78.99 0 top
C1082  SC1U6D3V2KX-GP  [C402H22]  95.58 78.99 0 top
C1083  SC1U6D3V2KX-GP  [C402H22]  96.47 78.99 0 top
C1084  SC1U6D3V2KX-GP  [C402H22]  97.36 78.99 0 top
C1085  SC1U6D3V2KX-GP  [C402H22]  98.24 78.99 0 top
C1086  SC1U6D3V2KX-GP  [C402H22]  99.13 78.99 0 top
C1087  SC1U6D3V2KX-GP  [C402H22]  100.02 78.99 0 top
C1088  SC1U6D3V2KX-GP  [C402H22]  93.29 83.02 180 top
C1089  SC1U6D3V2KX-GP  [C402H22]  95.07 81.22 0 top
C1090  SC1U6D3V2KX-GP  [C402H22]  95.07 83.02 180 top
C1091  SC1U6D3V2KX-GP  [C402H22]  97.1 81.35 0 top
C1092  SC180P50V2JN-1GP  [C402H22]  114.27 95.83 0 top
C1093  SC1U6D3V2KX-GP  [C402H22]  118.56 95.83 180 top
C1094  SC1U6D3V2KX-GP  [C402H22]  101.39 85.79 0 top
C1095  SC1U6D3V2KX-GP  [C402H22]  115.11 95.83 180 top
C1096  SC1U6D3V2KX-GP  [C402H22]  113.43 95.83 180 top
C1201  SCD1U10V2KX-5GP  [C402H22]  111.17 31.18 0 top
C1202  SC2D2U6D3V2MX-GP  [C402H22]  110.31 31.18 0 top
C1203  SC1KP50V2KX-1GP  [C402H22]  43.91 30.24 90 bottom
C1204  SCD1U10V2KX-5GP  [C402H22]  43.91 29.35 90 bottom
C1205  SC1KP50V2KX-1GP  [C402H22]  90.75 22.29 270 top
C1208  SC10U6D3V3MX-GP  [C603H38]  109.29 20.77 270 top
C1209  SC1U6D3V2KX-GP  [C402H22]  111.58 29.91 270 top
C1210  SC1U6D3V2KX-GP  [C402H22]  109.42 23.06 270 top
C1211  SC1U6D3V2KX-GP  [C402H22]  109.42 22.17 270 top
C1212  SC1U6D3V2KX-GP  [C402H22]  111.58 29.02 270 top
C1213  SC4D7U6D3V3KX-L-GP  [C603H36]  73.1 22.8 270 top
C1214  SCD1U10V2KX-5GP  [C402H22]  73.1 30.8 270 top
C1215  SC4D7U6D3V3KX-GP  [C603H36]  89.23 22.8 0 top
C1216  SC4D7U6D3V3KX-GP  [C603H36]  81.99 22.67 0 top
C1217  SCD1U10V2KX-5GP  [C402H22]  80.21 22.67 0 top
C1218  SC4D7U6D3V3KX-GP  [C603H36]  87.45 31.06 180 top
C1219  SC4D7U6D3V3KX-GP  [C603H36]  80.34 31.18 180 top
C1220  SC4D7U6D3V3KX-GP  [C603H36]  90.37 31.06 180 top
C1221  SC1KP50V2KX-1GP  [C402H22]  58.37 26.36 90 top
C1222  SCD1U10V2KX-5GP  [C402H22]  85.54 22.8 0 top
C1223  SCD1U10V2KX-5GP  [C402H22]  82.37 31.18 180 top
C1224  SCD1U10V2KX-5GP  [C402H22]  76.65 31.06 180 top
C1225  SCD1U10V2KX-5GP  [C402H22]  76.91 22.8 0 top
C1904  SC6D8P50V2DN-GP  [C402H22]  94.82 98.11 90 bottom
C1905  SC6D8P50V2DN-GP  [C402H22]  93.04 98.11 270 bottom
C2402  SCD1U10V2KX-5GP  [C402H22]  165.31 18.83 270 top
C2403  SCD1U10V2KX-5GP  [C402H22]  160.3 22.49 180 top
C2404  SCD1U10V2KX-5GP  [C402H22]  165.95 17.57 180 top
C2405  SC2D2U10V3KX-1GP  [C603H36]  164.91 17.22 180 top
C2406  SCD1U10V2KX-5GP  [C402H22]  160.79 31.41 270 bottom
C2407  SCD1U10V2KX-5GP  [C402H22]  160.79 32.3 270 bottom
C2408  SCD1U10V2KX-5GP  [C402H22]  181.68 30.55 0 top
C2409  SCD1U10V2KX-5GP  [C402H22]  171.39 37.63 0 bottom
C2410  SCD1U10V2KX-5GP  [C402H22]  180.85 30.55 0 top
C2411  SC2D2U10V3KX-1GP  [C603H36]  158.32 31.56 270 top
C2412  SCD1U10V2KX-5GP  [C402H22]  180.79 24.94 180 top
C2413  SC2D2U10V3KX-1GP  [C603H36]  181.87 24.91 180 top
C2414  SCD1U10V2KX-5GP  [C402H22]  162.89 20.26 90 top
C2415  SC220P50V2KX-3GP  [C402H22]  178.27 29.18 180 bottom
C2416  SC1U6D3V2KX-GP  [C402H22]  171.16 39.75 270 top
C2417  SCD1U10V2KX-5GP  [C402H22]  154.63 28.85 90 top
C2418  SC1U6D3V2KX-GP  [C402H22]  158.65 27.25 180 top
C2421  SC47P50V2JN-3GP  [C402H22]  188.05 35.69 0 top
C2501  SC10U6D3V3MX-GP  [C603H38]  154 36.52 180 bottom
C2502  SCD1U10V2KX-5GP  [C402H22]  154 38.42 270 bottom
C2503  SCD47U6D3V2KX-GP  [C402H22]  55.55 12.06 270 bottom
C2601  SC10U6D3V3MX-GP  [C603H38]  117.68 63.06 270 top
C2602  SCD1U10V2KX-5GP  [C402H22]  119.45 63.7 180 top
C2603  SC2200P50V2KX-2GP  [C402H22]  40.33 91.76 180 bottom
C2604  SC4D7U6D3V3KX-GP  [C603H36]  39.22 91.51 180 bottom
C2605  SCD1U10V2KX-5GP  [C402H22]  37.41 94.94 270 bottom
C2606  SC470P50V3JN-2GP  [C603H36]  53.16 46.17 0 top
C2607  SC2200P50V2KX-2GP  [C402H22]  119.33 61.79 0 top
C2608  SCD1U10V2KX-5GP  [C402H22]  67.89 85.67 180 top
C2609  SCD1U10V2KX-5GP  [C402H22]  67.89 83.99 0 top
C2610  SCD1U10V2KX-5GP  [C402H22]  154.84 23.46 90 top
C2611  SC4D7U6D3V3KX-GP  [C603H36]  37.79 93.79 270 bottom
C2615  SCD1U10V2KX-5GP  [C402H22]  129.11 63.44 180 top
C2616  SC100P50V2JN-3GP  [C402H22]  169.31 26.99 270 bottom
C2701  SC4D7U6D3V3KX-GP  [C603H36]  30.8 5.61 180 bottom
C2702  SC4D7U6D3V3KX-GP  [C603H36]  29.12 13.28 90 top
C2703  SC1U10V2KX-1GP  [C402H22]  30.86 6.55 0 top
C2704  SC1U10V2KX-1GP  [C402H22]  29.92 7.82 180 top
C2705  SC2D2U6D3V2MX-GP  [C402H22]  29.47 12.23 90 top
C2706  SC4D7U6D3V3KX-GP  [C603H36]  36.14 2.99 0 top
C2707  SCD1U10V2KX-5GP  [C402H22]  37.28 3.12 0 top
C2708  SC4D7U6D3V3KX-GP  [C603H36]  38.94 2.68 270 top
C2709  SCD1U10V2KX-5GP  [C402H22]  35 3.12 0 top
C2710  SCD1U10V2KX-5GP  [C402H22]  29.03 15.18 180 top
C2711  SC4D7U6D3V3KX-GP  [C603H36]  30.14 15.14 180 top
C2712  SC10U6D3V3MX-GP  [C603H38]  30.43 4.13 180 top
C2713  SC10U6D3V3MX-GP  [C603H38]  32.92 18.41 180 top
C2715  SC4D7U6D3V3KX-GP  [C603H36]  33.4 4.26 0 top
C2716  SC4D7U6D3V3KX-GP  [C603H36]  41.74 5.77 90 top
C2717  SCD1U10V2KX-5GP  [C402H22]  40.08 6.55 180 top
C2718  SC4D7U6D3V3KX-GP  [C603H36]  41.98 11.63 90 top
C2719  SCD1U10V2KX-5GP  [C402H22]  41.86 13.66 90 top
C2720  SCD1U10V2KX-5GP  [C402H22]  39.62 16.35 270 top
C2723  SC22P50V2JN-4GP  [C402H22]  43.29 8.43 270 top
C2901  SC1U6D3V2KX-GP  [C402H22]  41.35 17.21 270 top
C2902  SC10U6D3V3MX-GP  [C603H38]  18.49 8.7 180 bottom
C2907  SC4D7U6D3V3KX-GP  [C603H36]  29.92 17.08 270 top
C2908  SC4D7U6D3V3KX-GP  [C603H36]  29.92 18.36 270 top
C3001  SC15P50V2JN-2-GP  [C402H22]  31.44 44.39 180 bottom
C3002  SCD1U10V2KX-5GP  [C402H22]  32.6 41.08 180 bottom
C3003  SCD1U10V2KX-4GP  [C402H20]  31.62 37.16 180 bottom
C3004  SC4D7U6D3V3KX-GP  [C603H36]  34.36 50.61 180 top
C3005  SC4D7U6D3V3KX-GP  [C603H36]  40.08 45.79 0 bottom
C3007  SCD1U10V2KX-4GP  [C402H20]  37.67 45.15 270 top
C3008  SCD1U10V2KX-4GP  [C402H20]  32.84 47.82 90 bottom
C3009  SCD1U10V2KX-5GP  [C402H22]  35.11 38.41 180 bottom
C3010  SC4D7U6D3V3KX-GP  [C603H36]  34.05 38.3 180 bottom
C3011  SC15P50V2JN-2-GP  [C402H22]  31.44 46.17 0 bottom
C3012  SC4D7U6D3V3KX-GP  [C603H36]  35.13 38.68 0 top
C3013  SCD1U10V2KX-5GP  [C402H22]  39.47 51.45 180 top
C3014  SCD1U10V2KX-5GP  [C402H22]  39.98 41.6 270 bottom
C3015  SC1U10V2KX-1GP  [C402H22]  43.63 48.33 270 top
C3016  SCD1U10V2KX-5GP  [C402H22]  39.98 40.71 270 bottom
C3017  SCD1U10V2KX-4GP  [C402H20]  33.22 50.49 180 top
C3018  SC1U10V2KX-1GP  [C402H22]  35.58 42.19 180 top
C3019  SCD1U10V2KX-4GP  [C402H20]  33.98 38.8 0 top
C3021  SCD1U10V2KX-4GP  [C402H20]  34.81 46.69 0 top
C3022  SCD1U10V2KX-4GP  [C402H20]  34.69 42.19 180 top
C3023  SCD1U10V2KX-4GP  [C402H20]  34.05 43.46 90 top
C3024  SCD1U10V2KX-4GP  [C402H20]  34.05 44.47 90 top
C3025  SCD1U10V2KX-4GP  [C402H20]  34.05 45.36 90 top
C3101  SC100P3KV8JN-2-GP  [C1808H56]  24.61 44.01 0 top
C3106  SCD01U50V2KX-1GP  [C402H22]  32.33 50.49 180 top
C3401  SC4D7P50V2CN-1GP  [C402H22]  22.58 28.95 0 bottom
C3402  SC4D7P50V2CN-1GP  [C402H22]  22.58 27.17 180 bottom
C3403  SCD1U10V2KX-5GP  [C402H22]  28.78 27.47 90 bottom
C3404  SCD1U10V2KX-5GP  [C402H22]  28.78 28.36 90 bottom
C3405  SCD1U16V2KX-3GP  [C402H22]  18.06 27.14 0 top
C3406  SCD1U16V2KX-3GP  [C402H22]  17.14 39.64 0 top
C3503  SCD1U10V2KX-4GP  [C402H20]  18.16 44.98 90 top
C3504  SCD1U16V2KX-3GP  [C402H22]  145.62 5.76 180 bottom
C3505  SC1U10V3KX-3GP  [C603H36]  35.3 29.51 0 top
C3506  SC1U10V3KX-3GP  [C603H36]  18.21 39.69 0 top
C3507  SCD1U10V2KX-5GP  [C402H22]  18.95 27.12 0 top
C3508  SC1U10V3KX-3GP  [C603H36]  22.76 30.95 180 top
C3509  SC22U6D3V5MX-2GP  [C805H58]  18.72 43.6 90 top
C3510  SC1U10V3KX-3GP  [C603H36]  146.68 5.45 180 bottom
C3512  SC22U6D3V5MX-2GP  [C805H58]  21.18 27.53 0 top
C3513  SC22U6D3V5MX-2GP  [C805H58]  21.18 30.88 180 top
C3514  SC22U6D3V5MX-2GP  [C805H58]  26.08 33.09 0 top
C3515  SC22U6D3V5MX-2GP  [C805H58]  186.13 5.15 180 bottom
C3516  SC22U6D3V5MX-2GP  [C805H58]  184.22 5.15 180 bottom
C3517  SCD1U10V2KX-5GP  [C402H22]  159.33 5 180 bottom
C3518  SC1U10V3KX-3GP  [C603H36]  161.36 5.12 180 bottom
C3601  SC1KP50V2KX-1GP  [C402H22]  131.58 2.51 0 top
C3602  SC1KP50V2KX-1GP  [C402H22]  132.47 2.51 0 top
C3603  SC10U6D3V3MX-GP  [C603H38]  128.63 3.48 0 top
C3605  SC10U6D3V3MX-GP  [C603H38]  136.03 5.97 180 top
C3607  SC1U10V2KX-1GP  [C402H22]  41.78 13.12 270 bottom
C3612  SC1U10V2KX-1GP  [C402H22]  29.08 20.74 0 top
C3613  SC1U10V2KX-1GP  [C402H22]  136.47 65.85 270 bottom
C3617  SC1U10V2KX-1GP  [C402H22]  133.68 60.39 90 bottom
C3618  SC1KP50V2KX-1GP  [C402H22]  127.96 63.57 90 bottom
C3619  SC1KP50V2KX-1GP  [C402H22]  127.96 64.46 90 bottom
C3620  SC10U6D3V3MX-GP  [C603H38]  128.34 65.85 270 bottom
C3621  SC10U6D3V3MX-GP  [C603H38]  130.5 61.03 90 bottom
C3625  SCD1U10V2KX-5GP  [C402H22]  139.14 65.47 180 top
C3626  SCD1U10V2KX-5GP  [C402H22]  137.87 62.3 90 top
C5201  SCD1U10V2KX-5GP  [C402H22]  48.79 78.76 90 top
C5202  SC1KP50V2KX-1GP  [C402H22]  52.02 84.78 180 top
C5203  SCD1U10V2KX-5GP  [C402H22]  40.82 77.85 180 top
C5204  SC4D7U6D3V3KX-GP  [C603H36]  50.98 72.71 90 top
C5205  SCD1U25V3KX-GP  [C603H36]  53.16 84.78 0 top
C5206  SC1U6D3V2KX-GP  [C402H22]  48.79 79.57 270 top
C5207  SC4D7U6D3V3KX-GP  [C603H36]  24.05 85.11 0 bottom
C5208  SC10P50V2JN-4GP  [C402H22]  33.98 83.88 0 bottom
C5209  SCD1U10V2KX-5GP  [C402H22]  41.84 77.9 180 top
C5210  SCD1U10V2KX-5GP  [C402H22]  39.93 77.85 180 top
C5211  SCD1U10V2KX-5GP  [C402H22]  38.71 77.79 180 top
C5212  SCD1U10V2KX-5GP  [C402H22]  42.73 77.9 180 top
C5213  SCD1U10V2KX-5GP  [C402H22]  37.82 77.79 180 top
C5214  SC10P50V2JN-4GP  [C402H22]  32.01 83.92 0 bottom
C5401  SCD1U10V2KX-5GP  [C402H22]  15.44 95.19 0 bottom
C5402  SCD1U10V2KX-5GP  [C402H22]  19.89 78.55 90 bottom
C5403  SCD1U10V2KX-5GP  [C402H22]  19.89 77.67 90 bottom
C5404  SCD1U10V2KX-5GP  [C402H22]  19.89 80.59 90 bottom
C5405  SCD1U10V2KX-5GP  [C402H22]  19.89 79.7 90 bottom
C5406  SCD1U10V2KX-5GP  [C402H22]  19.8 81.98 90 bottom
C5407  SCD1U10V2KX-5GP  [C402H22]  19.89 84.9 90 bottom
C5408  SCD1U10V2KX-5GP  [C402H22]  19.89 84.02 90 bottom
C5409  SCD1U10V2KX-5GP  [C402H22]  19.8 82.87 90 bottom
C5602  SCD01U16V2KX-3GP  [C402H22]  187.91 9.21 90 bottom
C5603  SCD01U16V2KX-3GP  [C402H22]  187.91 10.1 90 bottom
C5605  SC10U10V5KX-2GP  [C805H54]  189.99 29.84 270 top
C5606  SCD1U10V2KX-5GP  [C402H22]  190.18 31.16 270 top
C5607  SCD01U16V2KX-3GP  [C402H22]  192.61 70.81 90 bottom
C5608  SCD01U16V2KX-3GP  [C402H22]  192.61 71.7 90 bottom
C5609  SC10U6D3V3MX-GP  [C603H38]  195.91 70.17 90 top
C5610  SC10U6D3V3MX-GP  [C603H38]  192.99 79.95 270 top
C5611  SCD01U16V2KX-3GP  [C402H22]  192.61 69.54 90 bottom
C5612  SCD01U16V2KX-3GP  [C402H22]  192.61 68.65 90 bottom
C5615  SCD01U16V2KX-3GP  [C402H22]  187.89 11.85 270 bottom
C5616  SCD01U16V2KX-3GP  [C402H22]  187.89 10.96 270 bottom
C5802  SCD1U10V2KX-5GP  [C402H22]  179.4 14.55 90 bottom
C5803  SC10U6D3V3MX-GP  [C603H38]  182.06 13.28 270 bottom
C5804  SCD1U10V2KX-5GP  [C402H22]  180.67 42.37 0 top
C5807  SCD1U10V2KX-5GP  [C402H22]  185.62 40.96 270 top
C6202  SCD1U10V2KX-5GP  [C402H22]  136.98 80.36 90 top
C6203  SCD1U10V2KX-5GP  [C402H22]  141.42 79.32 90 top
C6204  SCD1U10V2KX-5GP  [C402H22]  127.84 99.76 0 top
C6401  SCD047U16V2KX-1-GP  [C402H22]  12.03 74.63 90 top
C6402  SCD1U10V2KX-5GP  [C402H22]  12.01 75.51 90 top
C7301  SCD1U10V2KX-5GP  [C402H22]  146.38 109.54 270 top
C7302  SCD1U10V2KX-5GP  [C402H22]  146.38 108.65 270 top
C7303  SCD1U10V2KX-5GP  [C402H22]  149.93 110.43 270 top
C7304  SCD1U10V2KX-5GP  [C402H22]  149.93 111.32 270 top
C7305  SCD1U10V2KX-5GP  [C402H22]  146.38 112.21 270 top
C7306  SCD1U10V2KX-5GP  [C402H22]  146.38 113.1 270 top
C7307  SCD1U10V2KX-5GP  [C402H22]  149.93 113.99 270 top
C7308  SCD1U10V2KX-5GP  [C402H22]  149.93 114.88 270 top
C7333  SC47P50V2JN-3GP  [C402H22]  158.82 100.65 270 bottom
C7401  SC120P50V2JN-1GP  [C402H22]  173.05 153.61 270 top
C7402  SC1U10V2KX-1GP  [C402H22]  150.31 125.29 0 top
C7403  SC1U10V2KX-1GP  [C402H22]  151.2 127.07 180 top
C7406  SCD1U10V2KX-5GP  [C402H22]  174.19 123.18 90 top
C7407  SCD1U10V2KX-5GP  [C402H22]  179.52 118.69 270 bottom
C7515  SCD1U10V2KX-5GP  [C402H22]  163.8 108.6 270 top
C7516  SCD01U25V2KX-L1-GP  [C402H22]  162.18 102.89 0 bottom
C7517  SCD082U16V2KX-GP  [C402H22]  161.36 111.96 90 top
C7518  SCD68U16V3KX-GP-U  [C603H36]  165.94 107.51 270 top
C7519  SCD68U16V3KX-GP-U  [C603H36]  161.62 107.64 180 top
C7521  SC1U6D3V2KX-GP  [C402H22]  163.8 107.76 270 top
C7582  SC10U6D3V3MX-GP  [C603H38]  163.45 106.7 270 top
C7602  SC10U6D3V3MX-GP  [C603H38]  164.26 120.97 270 top
C7604  SC1U6D3V2KX-GP  [C402H22]  158.82 119.58 90 top
C7605  SC1U6D3V2KX-GP  [C402H22]  158.82 120.39 90 top
C7607  SC2D2U6D3V2MX-GP  [C402H22]  167 122.17 180 top
C7608  SC2D2U6D3V2MX-GP  [C402H22]  167.82 122.17 180 top
C7609  SC2D2U6D3V2MX-GP  [C402H22]  160.98 123 0 top
C7610  SC10U6D3V3MX-GP  [C603H38]  170.69 123.55 90 top
C7611  SCD01U16V2KX-3GP  [C402H22]  156.03 107.26 0 top
C7612  SC1U6D3V2KX-GP  [C402H22]  156.92 107.26 0 top
C7613  SC10U6D3V3MX-GP  [C603H38]  158.06 107.64 0 top
C7615  SC1U6D3V2KX-GP  [C402H22]  157.05 119.96 180 top
C7616  SC1U6D3V2KX-GP  [C402H22]  161.11 118.94 270 top
C7617  SC1U6D3V2KX-GP  [C402H22]  161.11 118.05 270 top
C7618  SC1U6D3V2KX-GP  [C402H22]  163.35 116.15 90 top
C7619  SC1U6D3V2KX-GP  [C402H22]  163.35 116.96 90 top
C7620  SC1U6D3V2KX-GP  [C402H22]  163.35 117.77 90 top
C7621  SC1U6D3V2KX-GP  [C402H22]  163.35 118.58 90 top
C7622  SC1U6D3V2KX-GP  [C402H22]  163.35 119.4 90 top
C7623  SC10U6D3V3MX-GP  [C603H38]  147.17 129.13 270 bottom
C7624  SC2D2U6D3V2MX-GP  [C402H22]  159.08 121.86 90 top
C7625  SC2D2U6D3V2MX-GP  [C402H22]  161.74 121.15 90 top
C7631  SCD1U10V2KX-5GP  [C402H22]  155.14 107.26 0 top
C7633  SC1U6D3V2KX-GP  [C402H22]  161.19 116.78 270 top
C7634  SC10U6D3V3MX-GP  [C603H38]  161.31 120.08 270 top
C7635  SC1U6D3V2KX-GP  [C402H22]  165.05 119.5 0 top
C7636  SC1U6D3V2KX-GP  [C402H22]  167.79 113.35 180 top
C7637  SC1U6D3V2KX-GP  [C402H22]  166.32 116.27 90 top
C7638  SC1U6D3V2KX-GP  [C402H22]  166.32 117.75 90 top
C7639  SC1U6D3V2KX-GP  [C402H22]  158.95 117.47 90 top
C7640  SC10U6D3V3MX-GP  [C603H38]  156.84 117.37 0 top
C7644  SC1U6D3V2KX-GP  [C402H22]  166.32 118.56 90 top
C7645  SC1U6D3V2KX-GP  [C402H22]  166.32 119.96 90 top
C7646  SC1U6D3V2KX-GP  [C402H22]  166.32 120.85 90 top
C7647  SC22U6D3V3MX-1-GP  [C603H40]  181.05 98.62 180 bottom
C7648  SC22U6D3V3MX-1-GP  [C603H40]  179.65 98.62 180 bottom
C7649  SC22U6D3V3MX-1-GP  [C603H40]  182.45 98.62 180 bottom
C7650  SC22U6D3V3MX-1-GP  [C603H40]  176.35 98.49 0 top
C7651  SC1U6D3V2KX-GP  [C402H22]  166.7 114.37 180 top
C7652  SC10U6D3V3MX-GP  [C603H38]  165.83 102.18 90 bottom
C7653  SC1U6D3V2KX-GP  [C402H22]  164.06 112.29 90 top
C7654  SC1U6D3V2KX-GP  [C402H22]  165.53 103.24 90 bottom
C7658  SC1U6D3V2KX-GP  [C402H22]  165.43 114.37 180 top
C7659  SC1U6D3V2KX-GP  [C402H22]  164.54 114.37 180 top
C7660  SC1U6D3V2KX-GP  [C402H22]  163.65 114.37 180 top
C7661  SC1U6D3V2KX-GP  [C402H22]  162.76 114.37 180 top
C7662  SC1U6D3V2KX-GP  [C402H22]  174.95 98.24 180 bottom
C7663  SC1U6D3V2KX-GP  [C402H22]  178.51 98.37 180 bottom
C7664  SC1U6D3V2KX-GP  [C402H22]  177.62 98.37 180 bottom
C7665  SC1U6D3V2KX-GP  [C402H22]  176.35 98.24 180 bottom
C7666  SC22U6D3V3MX-1-GP  [C603H40]  174.95 98.49 0 top
C7667  SC1U6D3V2KX-GP  [C402H22]  169.06 121.53 270 top
C7668  SC1U6D3V2KX-GP  [C402H22]  169.06 120.72 270 top
C7669  SC1U6D3V2KX-GP  [C402H22]  169.06 119.83 270 top
C7670  SC1U6D3V2KX-GP  [C402H22]  169.06 118.94 270 top
C7671  SC1U6D3V2KX-GP  [C402H22]  169.06 118.05 270 top
C7672  SC1U6D3V2KX-GP  [C402H22]  169.06 117.16 270 top
C7673  SC1U6D3V2KX-GP  [C402H22]  173.81 98.24 0 top
C7674  SC1U6D3V2KX-GP  [C402H22]  173.81 98.24 180 bottom
C7675  SC1U6D3V2KX-GP  [C402H22]  169.06 114.5 270 top
C7676  SC1U6D3V2KX-GP  [C402H22]  169.06 113.61 270 top
C7677  SC1U6D3V2KX-GP  [C402H22]  169.06 116.27 270 top
C7678  SC1U6D3V2KX-GP  [C402H22]  169.06 115.38 270 top
C7679  SC10U6D3V3MX-GP  [C603H38]  158.62 102.43 0 bottom
C7680  SC1U6D3V2KX-GP  [C402H22]  161.36 113.73 90 top
C7681  SCD1U10V2KX-5GP  [C402H22]  161.36 112.84 90 top
C7682  SC10U6D3V3MX-GP  [C603H38]  158.68 118.52 90 top
C7683  SC1U6D3V2KX-GP  [C402H22]  164.06 113.1 90 top
C7684  SC10U6D3V3MX-GP  [C603H38]  183.08 125.16 0 bottom
C7685  SC1U6D3V2KX-GP  [C402H22]  181.94 125.42 0 bottom
C7686  SCD1U10V2KX-5GP  [C402H22]  181.05 125.42 0 bottom
C7687  SC10U6D3V3MX-GP  [C603H38]  183.08 127.7 180 bottom
C7688  SC1U6D3V2KX-GP  [C402H22]  181.94 127.32 180 bottom
C7689  SCD1U10V2KX-5GP  [C402H22]  181.05 127.32 180 bottom
C7729  SC10P50V2JN-4GP  [C402H22]  153.11 103.24 90 bottom
C7730  SC10P50V2JN-4GP  [C402H22]  156.66 103.24 270 bottom
C7779  SCD1U10V2KX-5GP  [C402H22]  173.81 121.35 0 top
C7780  SC1U6D3V2KX-GP  [C402H22]  175.59 121.35 0 top
C7781  SCD1U10V2KX-5GP  [C402H22]  174.7 121.35 0 top
C7787  SC1U6D3V2KX-L-1-GP  [C402H22]  168.22 108.53 270 top
C7788  SCD1U10V2KX-5GP  [C402H22]  168.22 109.42 270 top
C7790  SC1U6D3V2KX-L-1-GP  [C402H22]  168.35 102.81 0 bottom
C7791  SCD1U10V2KX-5GP  [C402H22]  167.46 102.81 0 bottom
C7792  SC10U6D3V3MX-GP  [C603H38]  168.35 107.38 270 top
C7793  SC10U6D3V3MX-GP  [C603H38]  169.49 102.56 0 bottom
C7801  SC10U6D3V3MX-GP  [C603H38]  162.51 153.87 0 bottom
C7802  SCD01U16V2KX-3GP  [C402H22]  158.57 153.23 0 bottom
C7803  SCD1U10V2KX-5GP  [C402H22]  155.9 153.23 0 bottom
C7808  SCD1U10V2KX-5GP  [C402H22]  161.24 153.23 0 bottom
C7810  SCD1U10V2KX-5GP  [C402H22]  160.47 137.23 180 bottom
C7811  SCD1U10V2KX-5GP  [C402H22]  159.46 153.23 0 bottom
C7812  SCD1U10V2KX-5GP  [C402H22]  152.35 153.23 0 bottom
C7813  SCD1U10V2KX-5GP  [C402H22]  151.46 153.23 0 bottom
C7814  SCD1U10V2KX-5GP  [C402H22]  160.35 153.23 0 bottom
C7816  SCD1U10V2KX-5GP  [C402H22]  164.03 153.23 180 top
C7817  SCD1U10V2KX-5GP  [C402H22]  155.9 153.23 180 top
C7818  SCD1U10V2KX-5GP  [C402H22]  162.25 137.23 180 bottom
C7819  SCD1U10V2KX-5GP  [C402H22]  149.68 153.23 0 bottom
C8301  SC470P50V2KX-3GP  [C402H22]  144.35 103.45 270 bottom
C8302  SC1KP50V2KX-1GP  [C402H22]  144.35 102.56 270 bottom
C8303  SC10U6D3V3MX-GP  [C603H38]  142.31 98.75 180 bottom
C8304  SC10U6D3V3MX-GP  [C603H38]  144.22 106.11 0 bottom
C8308  SCD1U10V2KX-5GP  [C402H22]  142.82 105.99 180 bottom
C8309  SCD1U10V2KX-5GP  [C402H22]  145.74 99.26 0 bottom
C8313  SCD1U10V2KX-5GP  [C402H22]  136.73 102.94 180 bottom
C8314  SCD1U10V2KX-5GP  [C402H22]  136.73 101.16 0 bottom
C8316  SC1U10V2KX-1GP  [C402H22]  139.9 99.51 270 bottom
C8320  SC1U10V2KX-1GP  [C402H22]  139.52 104.72 270 bottom
C8901  SCD1U10V2KX-5GP  [C402H22]  178.51 153.23 180 top
C8903  SCD01U16V2KX-3GP  [C402H22]  178.13 153.61 90 bottom
C8905  SC10U6D3V3MX-GP  [C603H38]  181.68 153.74 0 bottom
C8908  SCD1U10V2KX-5GP  [C402H22]  173.56 153.23 0 bottom
C8910  SCD1U10V2KX-5GP  [C402H22]  186.76 153.23 0 bottom
C8911  SCD1U10V2KX-5GP  [C402H22]  185.87 153.23 0 bottom
C8912  SCD1U10V2KX-5GP  [C402H22]  185.87 153.23 180 top
C8913  SCD1U10V2KX-5GP  [C402H22]  175.84 153.23 0 bottom
C8914  SCD1U10V2KX-5GP  [C402H22]  174.44 137.23 180 bottom
C8915  SCD1U10V2KX-5GP  [C402H22]  174.44 153.23 0 bottom
C8920  SCD1U10V2KX-5GP  [C402H22]  174.44 153.23 180 top
C8922  SCD1U10V2KX-5GP  [C402H22]  176.98 137.23 180 bottom
C8923  SCD1U10V2KX-5GP  [C402H22]  183.08 153.23 0 bottom
CCD1  ETY-CON8-16-GP  [4260-F08N-00R]  18.5 90.2 180 top
CPU1  BEEMA-GP  [BGA769M24D5H78]  97.6 82.55 270 bottom
D401  BAS16-6-GP  [SOT23-2D4-312H44]  65.73 85.29 0 bottom
D2401  RB751V-40H-GP  [SOD323AKH38]  186.67 24.94 90 top
D2501  BAS40-05-7-F-1-GP  [SOT23-2D4-312H48]  54.84 9.67 90 bottom
D2601  RB551V30-GP  [SOD323AKH38]  37.54 90.75 0 bottom
D2701  BAT54CPT-2-GP  [SOT23-2D6-312H46]  40.59 19.63 180 top
D3602  BAS16-6-GP  [SOT23-2D4-312H44]  152.78 21.4 270 top
D3603  BAS16-6-GP  [SOT23-2D4-312H44]  141.93 64.33 270 top
D3606  RB751V-40H-GP  [SOD323AKH38]  141.68 61.03 90 top
D4301  DA3X101F0L-1-GP  [SOT23-2D8-312H56]  141.68 142.94 90 top
D4302  DA3X101F0L-1-GP  [SOT23-2D8-312H56]  137.23 138.88 0 top
D4303  DA3X101F0L-1-GP  [SOT23-2D8-312H56]  140.79 138.88 0 top
D5201  BAT54CPT-2-GP  [SOT23-2D6-312H46]  53.48 77.82 90 top
D5202  RB551V30-GP  [SOD323AKH38]  43 87.19 90 bottom
D5401  BAW56-5-GP  [SOT-23-9H44]  24.97 89.22 180 bottom
D7301  BAW56-5-GP  [SOT-23-9H44]  161.74 99.13 270 bottom
DB1  PAD-10P-177042-GP  [PAD-10P-177042]  160.35 11.37 180 bottom
DCIN1  ACES-CON7-6-GP-U  [50299-00701-W01]  97.12 149.7 270 top
DM1  DDR3-204P-48-GP-U  [1932208-1-U]  81.9 26.82 180 bottom
EC2501  SC4D7P50V2CN-1GP  [C402H22]  157.55 38.42 270 bottom
EC2502  SC4D7P50V2CN-1GP  [C402H22]  148.34 38.53 270 bottom
EC2503  SC10P50V2JN-4GP  [C402H22]  155.78 38.42 90 bottom
EC2601  SCD1U10V2KX-5GP  [C402H22]  41.22 91.76 180 bottom
EC2602  SC10P50V2JN-4GP  [C402H22]  40.21 93.92 180 bottom
EC2701  SC10P50V2JN-4GP  [C402H22]  41.37 6.85 90 top
EC2703  SCD1U10V2KX-5GP  [C402H22]  33.93 20.92 180 top
EC2704  SC1KP50V2KX-1GP  [C402H22]  28.52 2.99 0 top
EC2705  SCD1U10V2KX-5GP  [C402H22]  34.94 20.9 180 top
EC2706  SC1KP50V2KX-1GP  [C402H22]  29.36 2.99 0 top
EC2707  SC1KP50V2KX-1GP  [C402H22]  37.08 18.84 90 top
EC2708  SCD1U10V2KX-5GP  [C402H22]  41.98 10.61 270 bottom
EC2709  SCD1U10V2KX-5GP  [C402H22]  43.03 10.5 90 top
EC2901  SC2K2P50V3KX-GP  [C603]  72.67 2.76 270 top
EC2902  SC2K2P50V3KX-GP  [C603]  77.53 4.52 180 top
EC2903  SC2K2P50V3KX-GP  [C603]  77.52 7.89 180 top
EC2904  SC2K2P50V3KX-GP  [C603]  76.19 5.87 0 top
EC2905  SC100P50V2JN-3GP  [C402H22]  19.25 6.42 180 top
EC2906  SC100P50V2JN-3GP  [C402H22]  26.74 10.61 90 top
EC2907  SC100P50V2JN-3GP  [C402H22]  28.01 10.23 180 top
EC2908  SC100P50V2JN-3GP  [C402H22]  27 13.28 90 top
EC3101  SC10P50V2JN-4GP  [C402H22]  36.27 52.65 0 bottom
EC3102  SC10P50V2JN-4GP  [C402H22]  36.27 54.42 180 bottom
EC3103  SC10P50V2JN-4GP  [C402H22]  36.27 56.2 0 bottom
EC3104  SC10P50V2JN-4GP  [C402H22]  36.27 57.98 180 bottom
EC3105  SC10P50V2JN-4GP  [C402H22]  36.27 57.98 0 top
EC3106  SC10P50V2JN-4GP  [C402H22]  36.27 56.2 180 top
EC3107  SC10P50V2JN-4GP  [C402H22]  36.27 54.42 0 top
EC3108  SC10P50V2JN-4GP  [C402H22]  36.27 52.65 180 top
EC4301  SC10P50V2JN-4GP  [C402H22]  143.2 140.28 180 top
EC4302  SC10P50V2JN-4GP  [C402H22]  141.3 136.34 90 top
EC4303  SCD1U25V2KX-GP  [C402H22]  141.15 149.98 270 bottom
EC4304  SCD1U25V3KX-GP  [C603H36]  127.28 150.84 90 bottom
EC4305  SC10P50V2JN-4GP  [C402H22]  137.11 136.34 90 top
EC4401  SC2200P50V2KX-2GP  [C402H22]  130.25 126.69 90 top
EC4402  SCD1U25V2KX-GP  [C402H22]  130.25 122.5 270 bottom
EC4601  SCD1U25V3KX-GP  [C603H36]  82.01 14.25 0 top
EC5205  SC6D8P50V2DN-GP  [C402H22]  30.12 86.56 0 bottom
EC5206  SC6D8P50V2DN-GP  [C402H22]  30.13 84.87 180 bottom
EC5210  SC33P50V2JN-3GP  [C402H22]  22.93 85.46 0 bottom
EC6103  SC220P50V2KX-3GP  [C402H22]  178.76 18.31 180 top
EC6104  SCD1U25V2KX-GP  [C402H22]  97.23 141.44 0 bottom
EC6105  SC220P50V2KX-3GP  [C402H22]  178.79 16.6 0 top
EC6205  SC33P50V2JN-3GP  [C402H22]  132.41 77.79 270 top
EC6206  SC33P50V2JN-3GP  [C402H22]  127.84 97.86 0 bottom
EC6207  SC33P50V2JN-3GP  [C402H22]  127.84 96.08 180 bottom
EC6208  SC33P50V2JN-3GP  [C402H22]  134.19 77.79 90 top
EC9701  SCD1U25V2KX-GP  [C402H22]  116.28 122.88 0 top
EC9703  SCD1U25V2KX-GP  [C402H22]  99.7 11.17 180 top
